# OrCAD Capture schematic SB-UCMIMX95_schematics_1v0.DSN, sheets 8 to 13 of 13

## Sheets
8 08. MIPI-CSI: size A3; title: MIPI-CSI
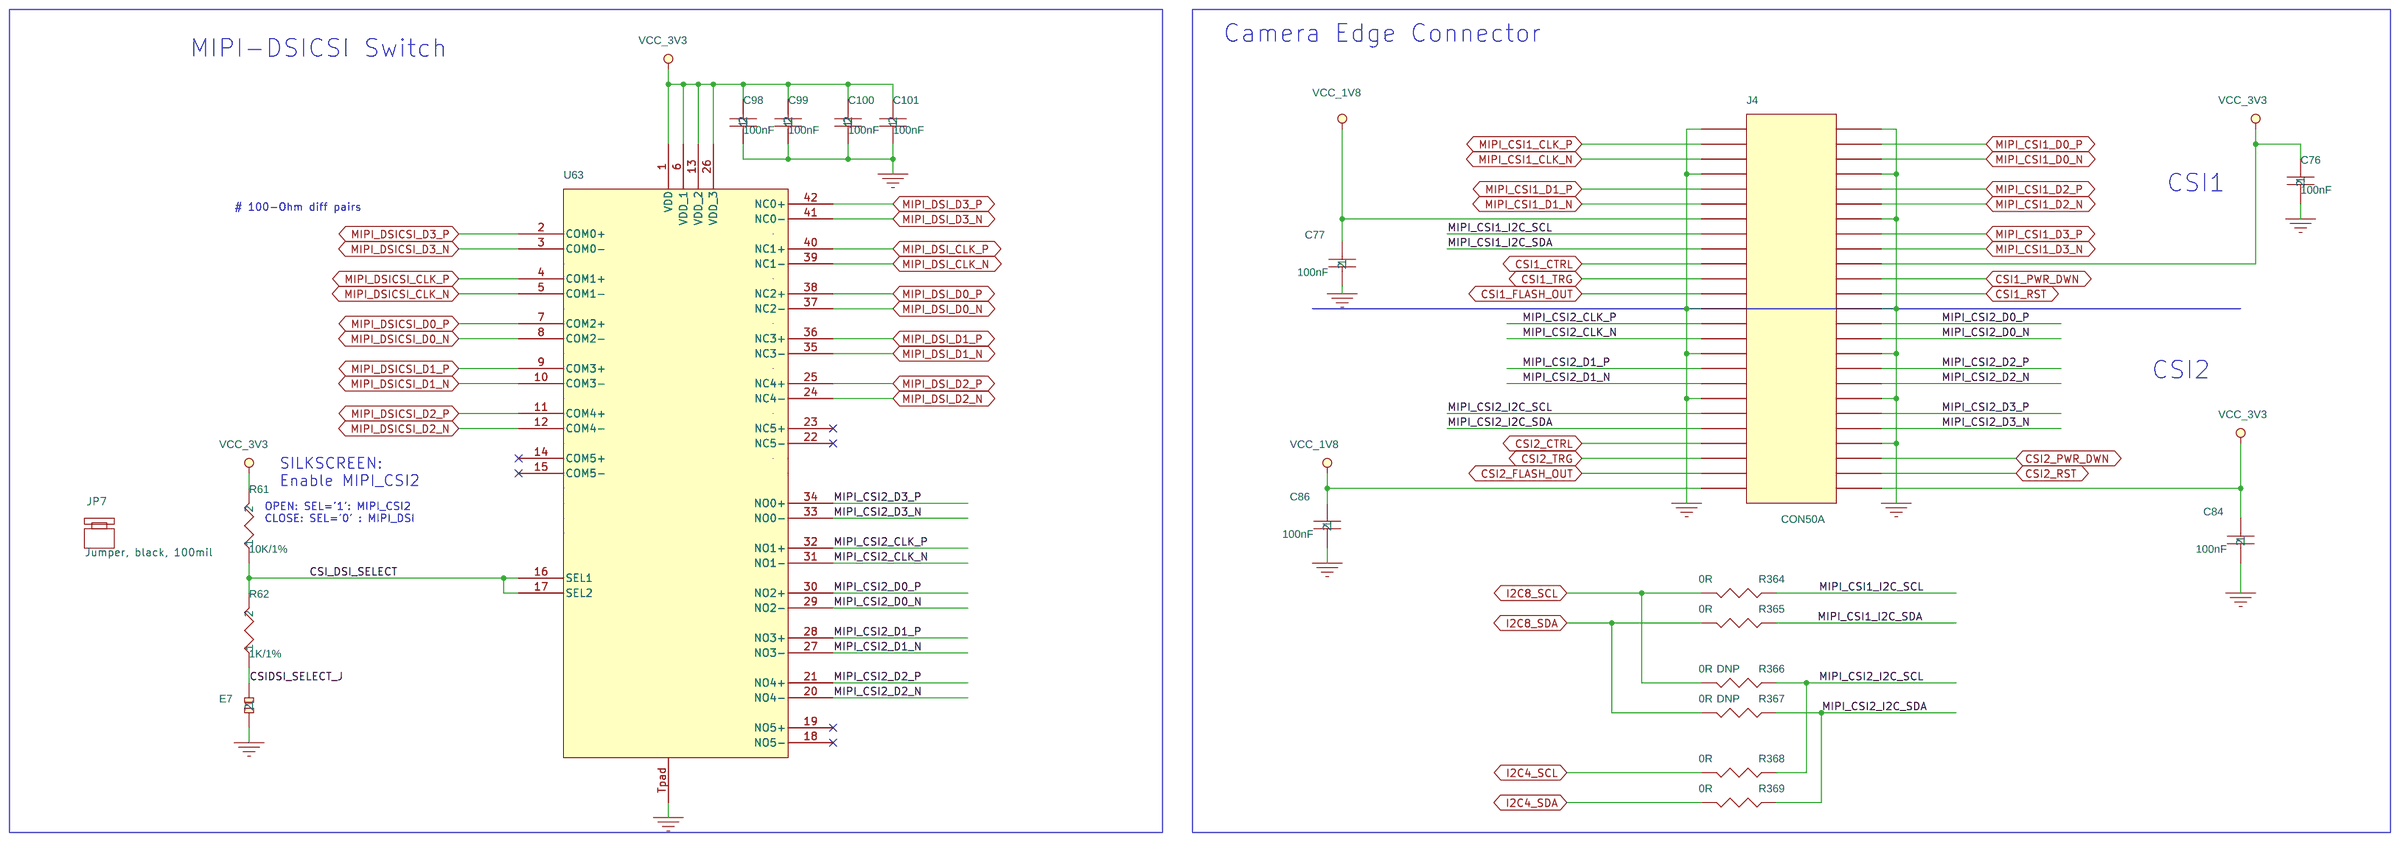
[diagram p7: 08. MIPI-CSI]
9 09. Audio Codec: size A3; title: Audio Codec
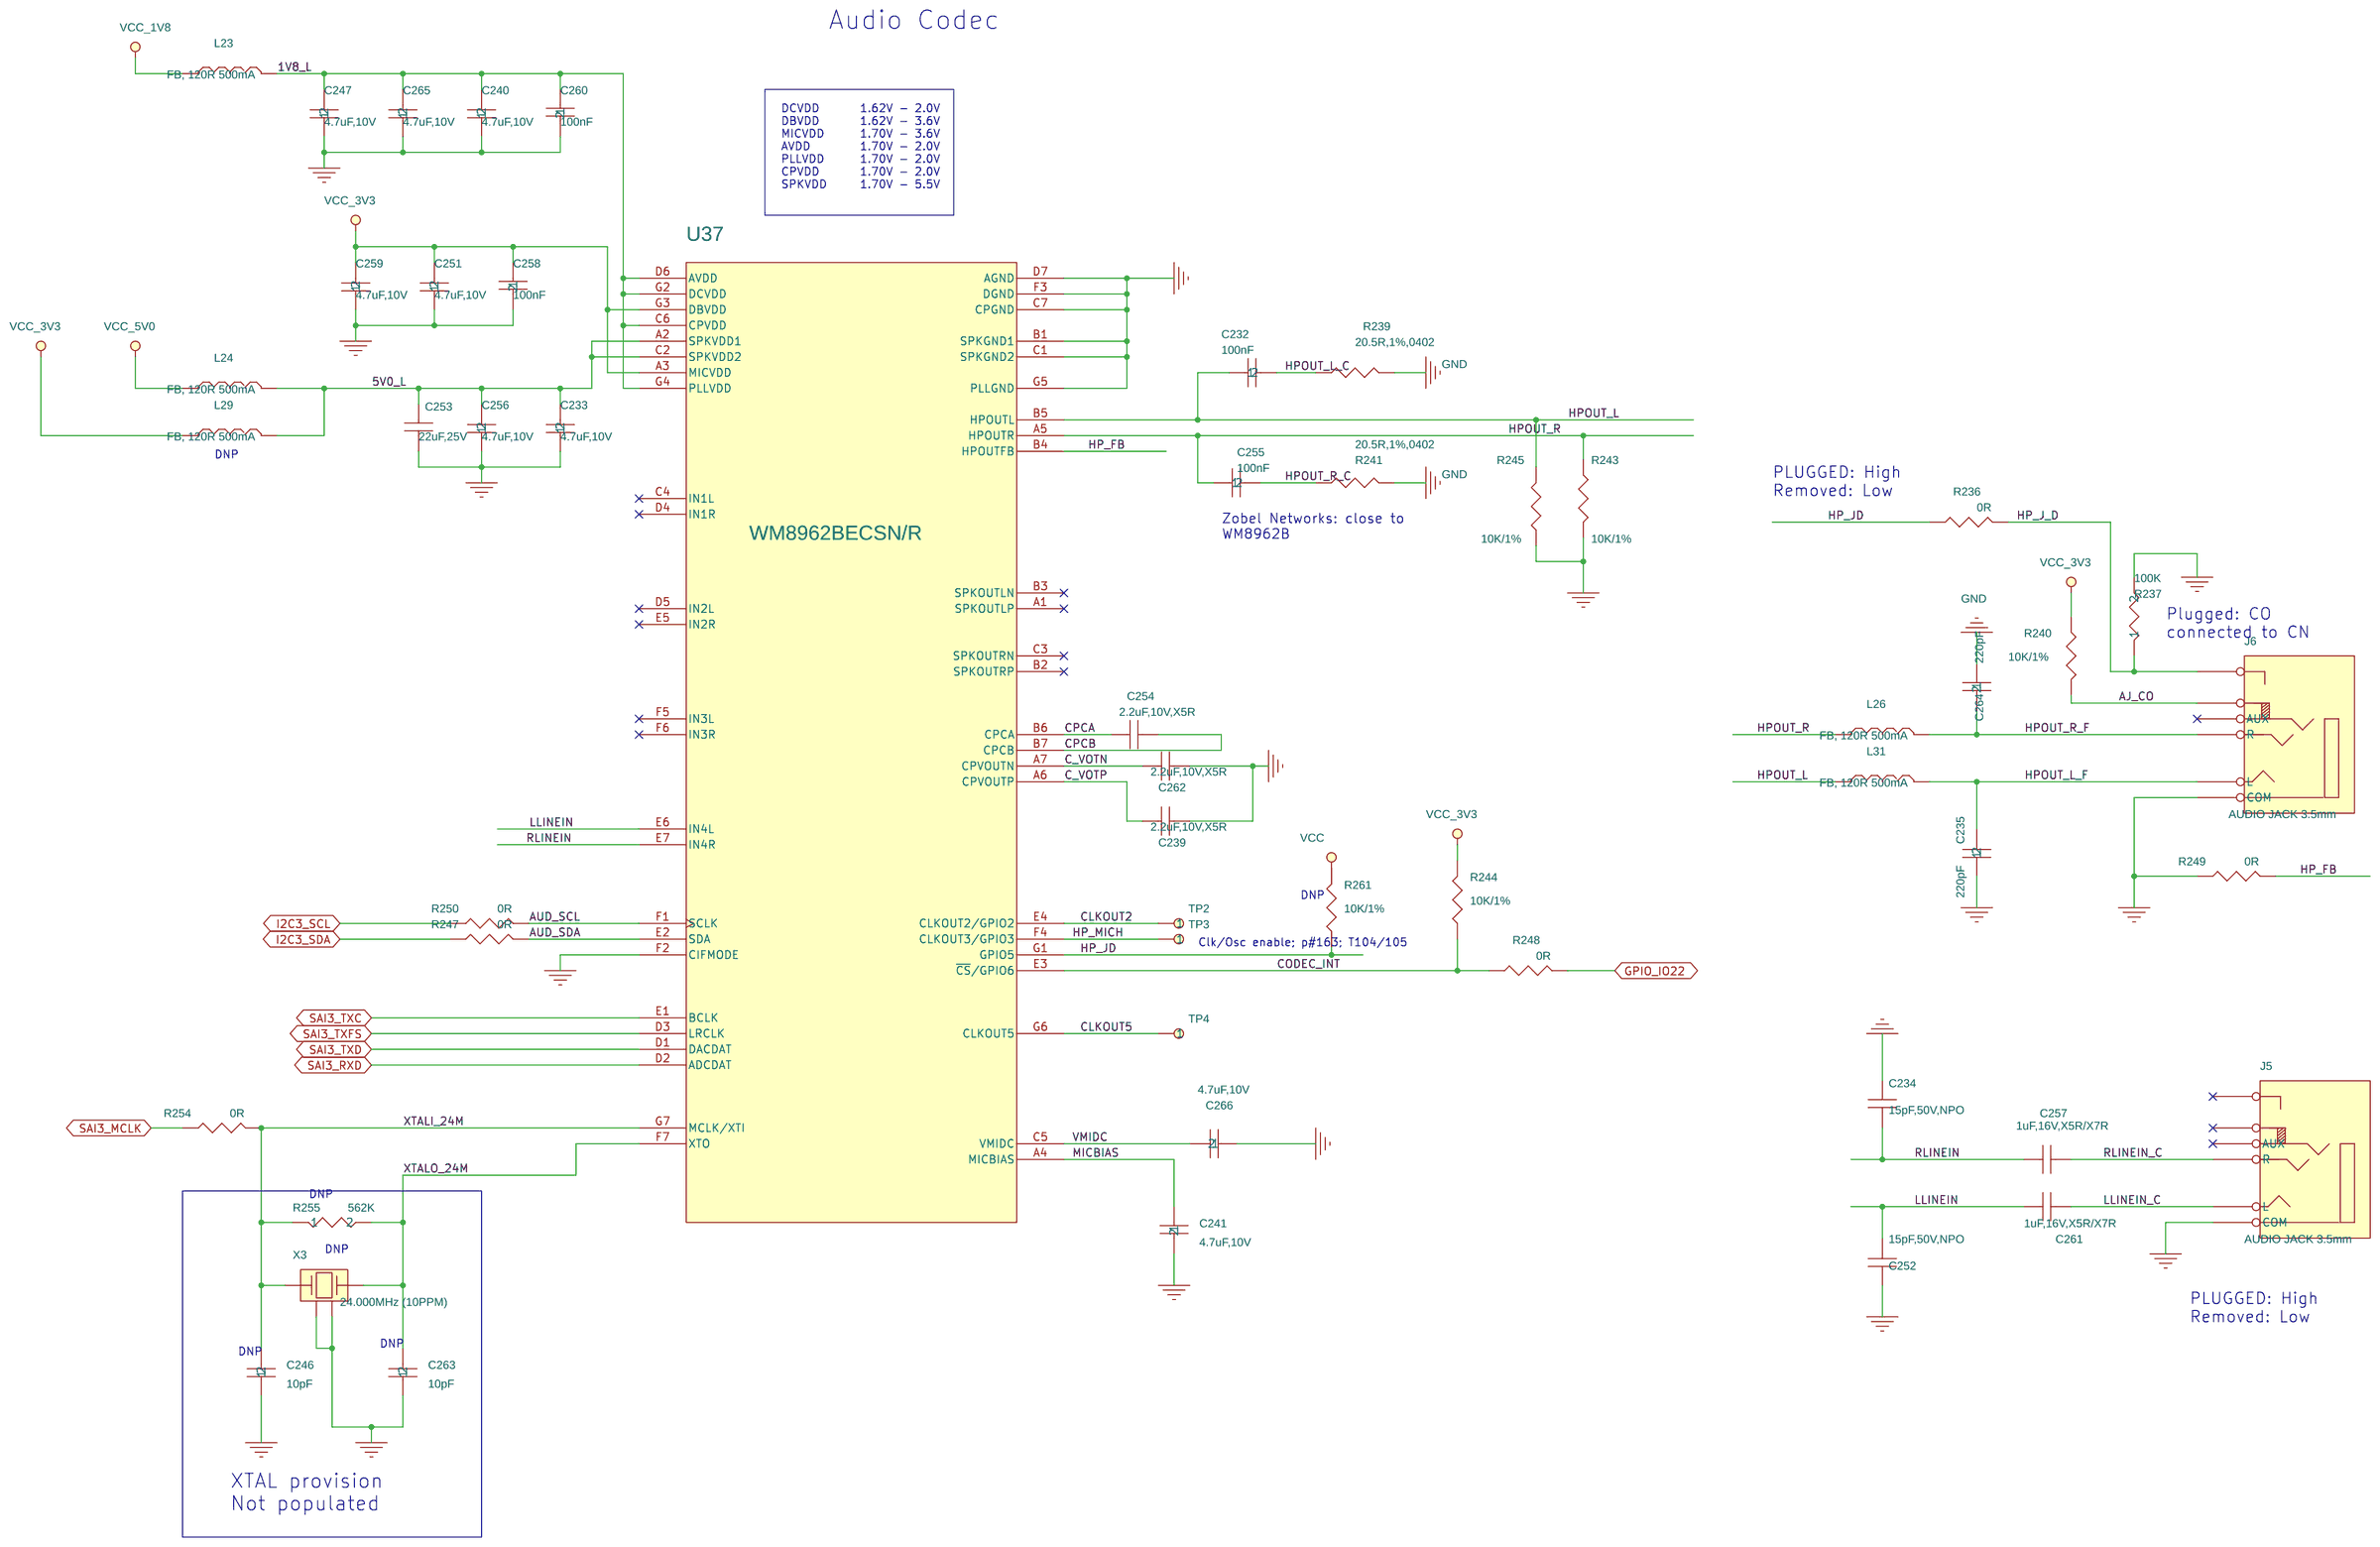
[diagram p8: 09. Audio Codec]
10 10. Octal SPI Flash, LEDs: size A3; title: Octal SPI Flash, LEDs
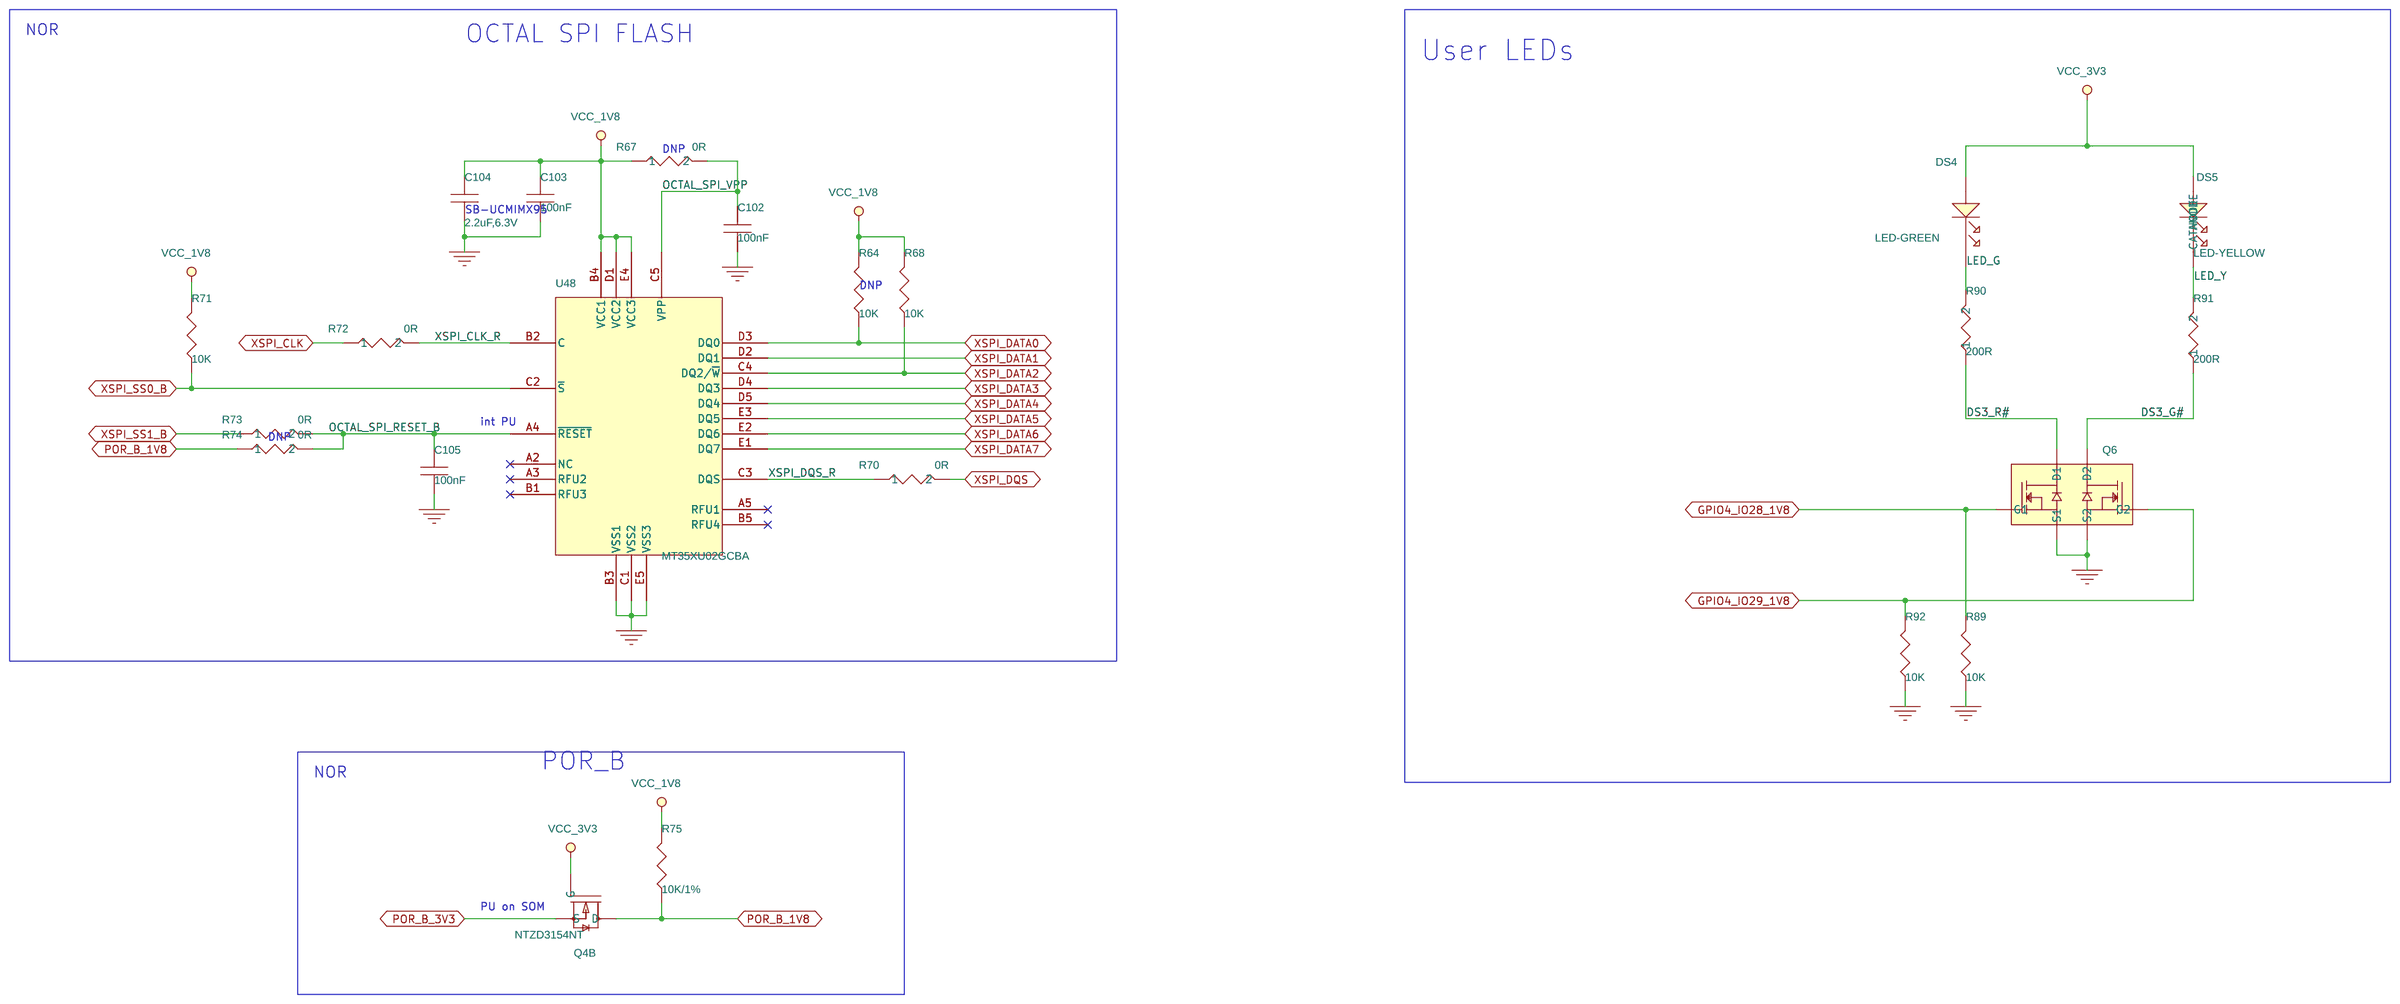
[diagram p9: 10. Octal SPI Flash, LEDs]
11 12. Power: size A3; title: Power
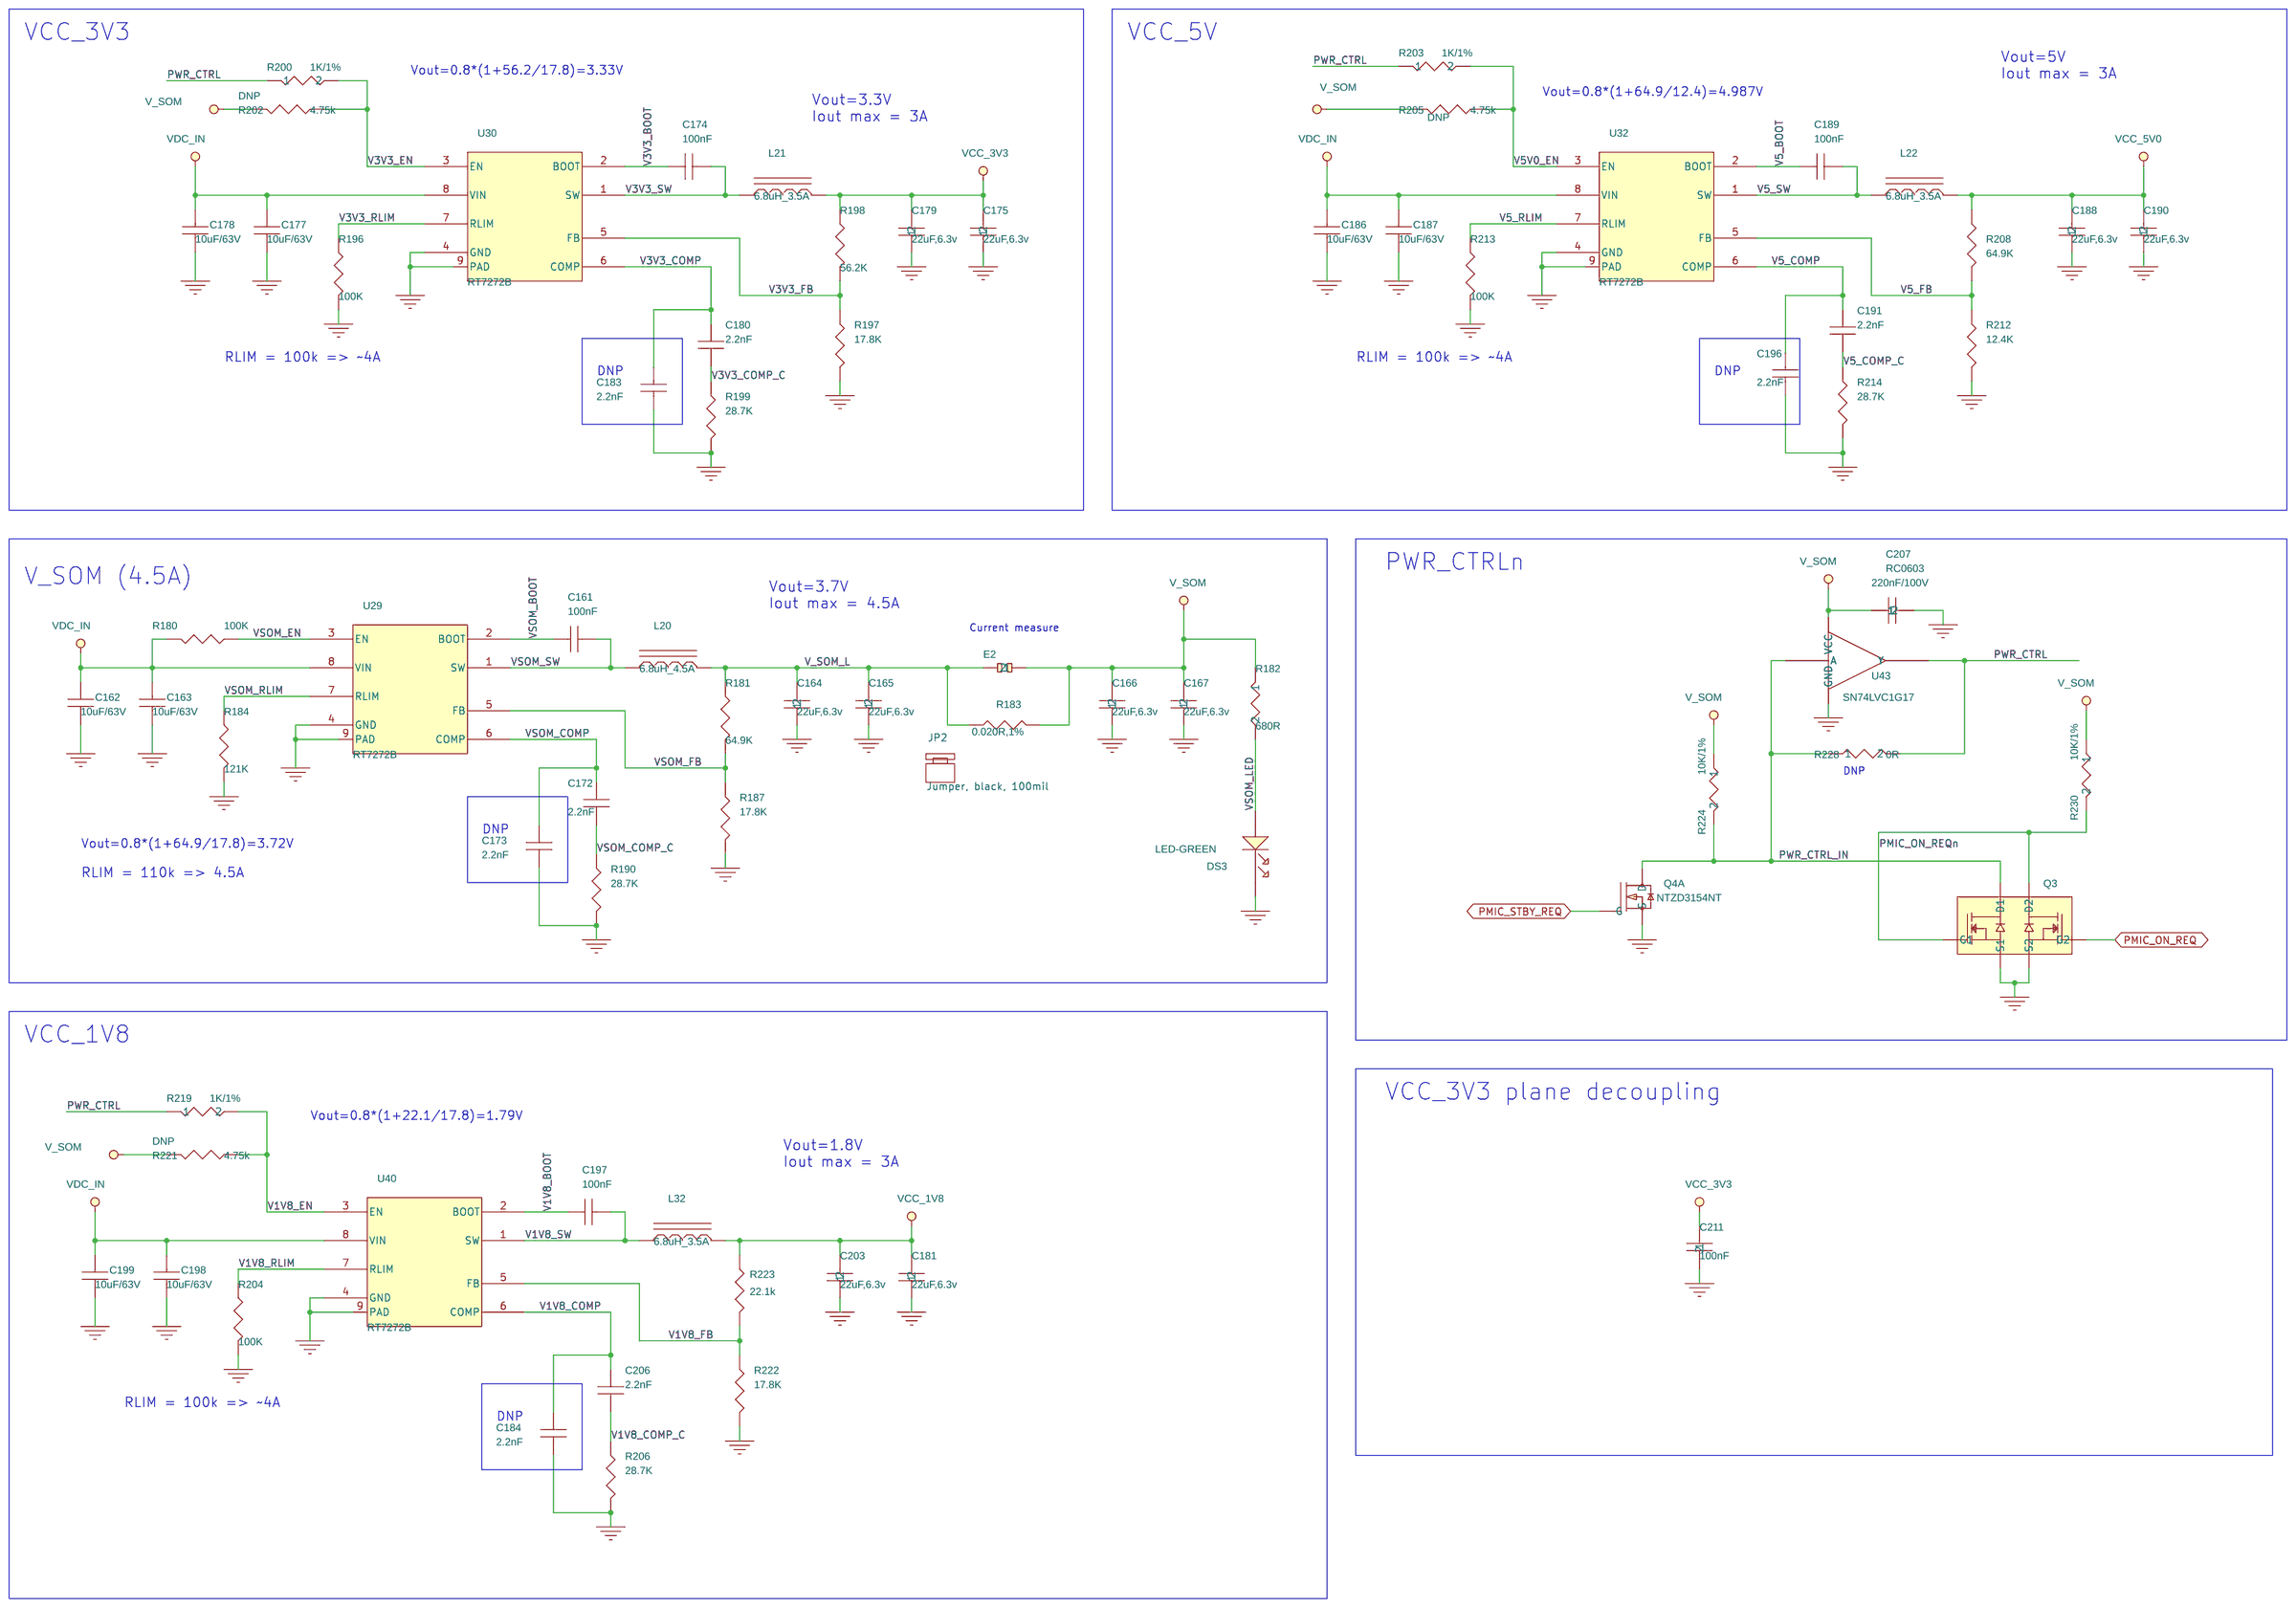
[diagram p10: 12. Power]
12 13. DC input and spacers: size A3; title: DC input and spacers
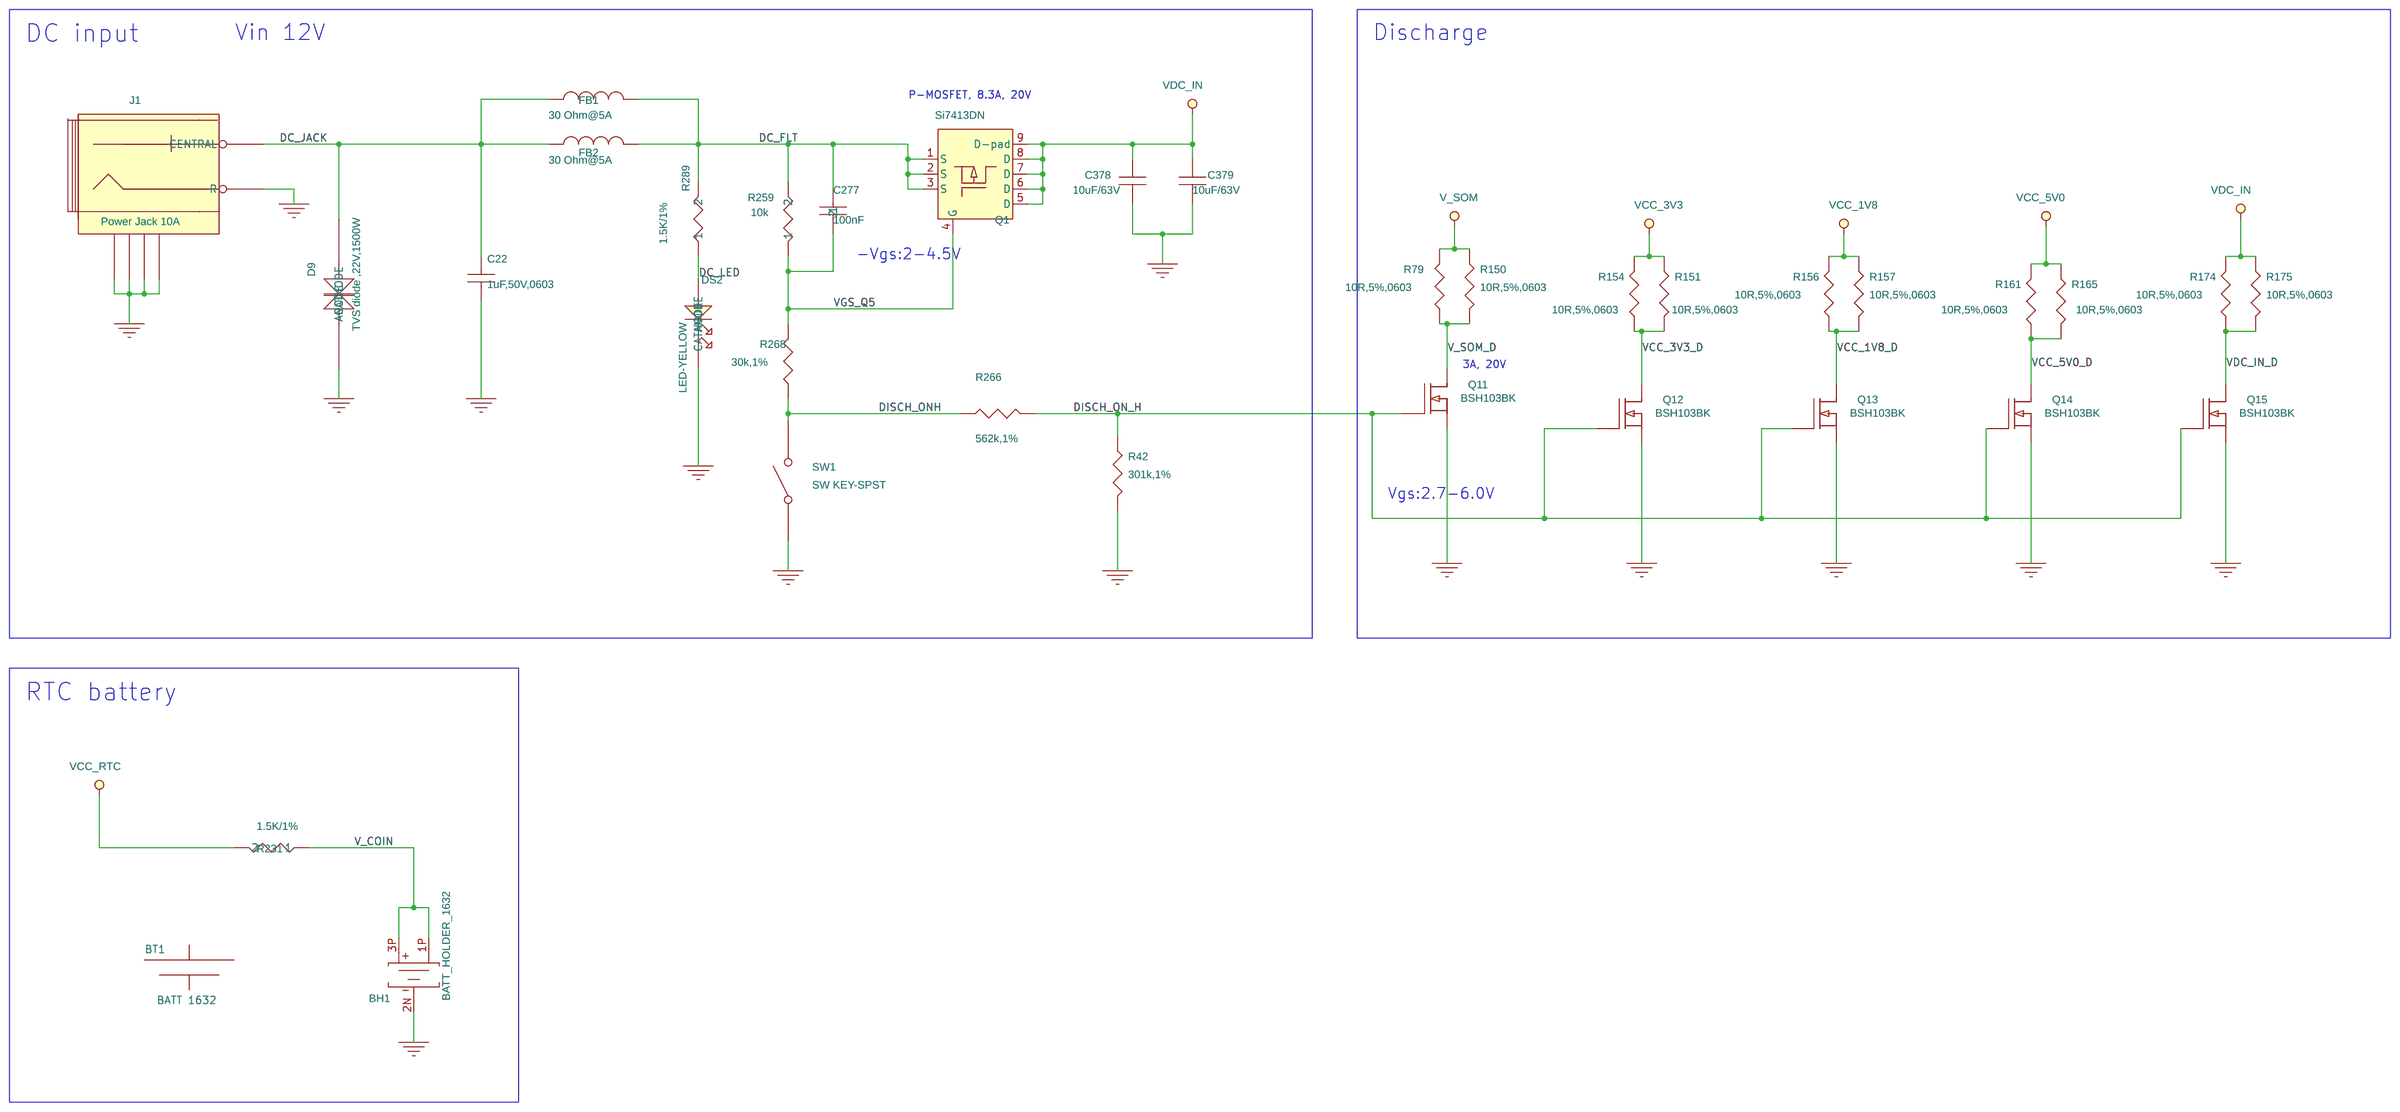
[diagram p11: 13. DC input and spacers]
13 11. I/O headers, JTAG, GPIO exp: size A3; title: I/O headers, JTAG, GPIO exp
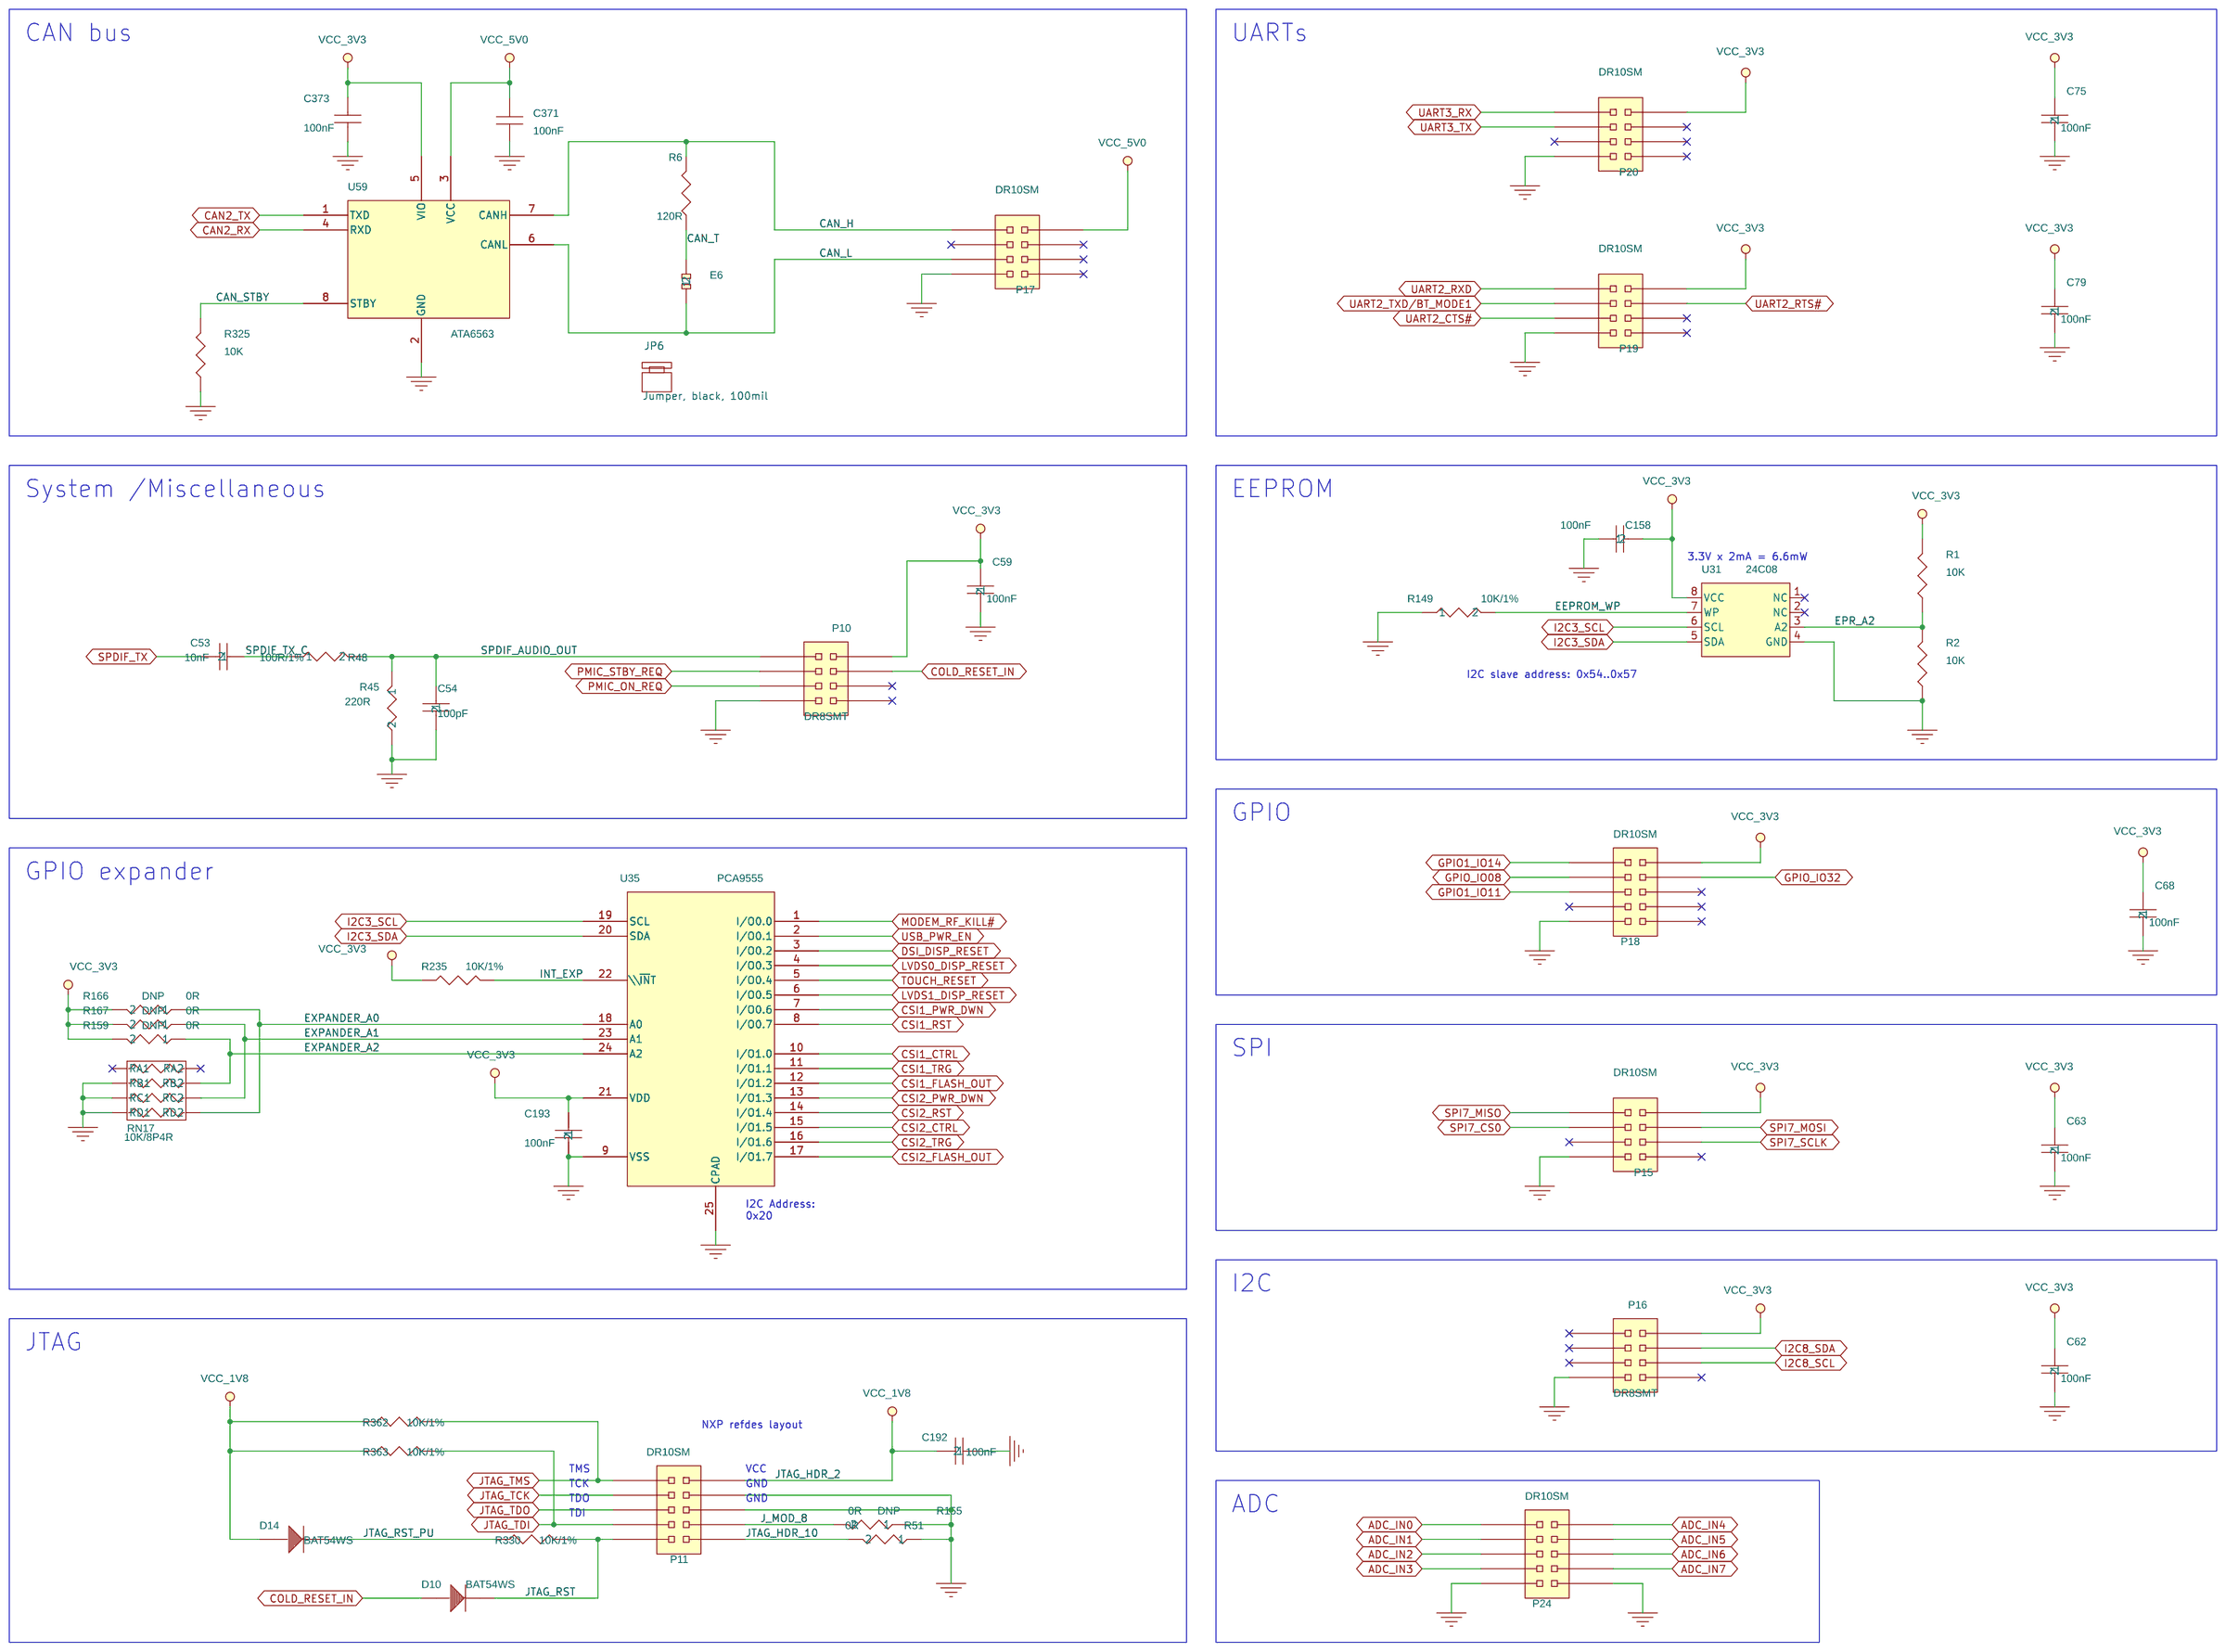
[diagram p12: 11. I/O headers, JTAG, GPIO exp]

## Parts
sheet 08. MIPI-CSI
C76  100nF  [RC0402]
C77  100nF  [RC0402]
C84  100nF  [RC0402]
C86  100nF  [RC0402]
C98  100nF  [RC0402]
C99  100nF  [RC0402]
C100  100nF  [RC0402]
C101  100nF  [RC0402]
E7  HDR1X2  [1X2THHDR]
J4  CON50A
JP7  Jumper, black, 100mil
R61  10K/1%  [RC0402]
R62  1K/1%  [RC0402]
R364  0R  [RC0402]
R365  0R  [RC0402]
R366  0R  [RC0402]
R367  0R  [RC0402]
R368  0R  [RC0402]
R369  0R  [RC0402]
U63  Value  [21-0181B_T423590M-1_MXM]
sheet 09. Audio Codec
C232  100nF  [RC0402]
C233  4.7uF,10V  [RC0402]
C234  15pF,50V,NPO  [RC0402]
C235  220pF  [RC0603]
C239  2.2uF,10V,X5R  [RC0402]
C240  4.7uF,10V  [RC0402]
C241  4.7uF,10V  [RC0402]
C246  10pF  [RC0402]
C247  4.7uF,10V  [RC0402]
C251  4.7uF,10V  [RC0402]
C252  15pF,50V,NPO  [RC0402]
C253  22uF,25V  [C0805]
C254  2.2uF,10V,X5R  [RC0402]
C255  100nF  [RC0402]
C256  4.7uF,10V  [RC0402]
C257  1uF,16V,X5R/X7R  [RC0402]
C258  100nF  [RC0402]
C259  4.7uF,10V  [RC0402]
C260  100nF  [RC0402]
C261  1uF,16V,X5R/X7R  [RC0402]
C262  2.2uF,10V,X5R  [RC0402]
C263  10pF  [RC0402]
C264  220pF  [RC0603]
C265  4.7uF,10V  [RC0402]
C266  4.7uF,10V  [RC0402]
J5  AUDIO JACK 3.5mm  [AJ35-4P-SW-SM]
J6  AUDIO JACK 3.5mm  [AJ35-4P-SW-SM]
L23  FB, 120R 500mA  [FB0402]
L24  FB, 120R 500mA  [FB0402]
L26  FB, 120R 500mA  [FB0402]
L29  FB, 120R 500mA  [FB0402]
L31  FB, 120R 500mA  [FB0402]
R236  0R  [RC0402]
R237  100K  [RC0402]
R239  20.5R,1%,0402  [RC0402]
R240  10K/1%  [RC0402]
R241  20.5R,1%,0402  [RC0402]
R243  10K/1%  [RC0402]
R244  10K/1%  [RC0402]
R245  10K/1%  [RC0402]
R247  0R  [RC0402]
R248  0R  [RC0402]
R249  0R  [RC0402]
R250  0R  [RC0402]
R254  0R  [RC0402]
R255  562K  [RC0402]
R261  10K/1%  [RC0402]
TP2  TESTPOINT SMT  [TESTPOINT]
TP3  TESTPOINT SMT  [TESTPOINT]
TP4  TESTPOINT SMT  [TESTPOINT]
U37  WM8962BECSN/R  [BGA49_0P5_3P62X4]
X3  24.000MHz (10PPM)  [OSC3225]
sheet 10. Octal SPI Flash, LEDs
C102  100nF  [RC0402]
C103  100nF  [RC0402]
C104  2.2uF,6.3V  [RC0402]
C105  100nF  [RC0402]
DS4  LED-GREEN  [LED-1206]
DS5  LED-YELLOW  [LED-1206]
Q6  0.5A,20V,Vgs max 6V  [SOT-563-6]
R64  10K  [RC0402]
R67  0R  [RC0402]
R68  10K  [RC0402]
R70  0R  [RC0402]
R71  10K  [RC0402]
R72  0R  [RC0402]
R73  0R  [RC0402]
R74  0R  [RC0402]
R75  10K/1%  [RC0402]
R89  10K  [RC0402]
R90  200R  [RC0402]
R91  200R  [RC0402]
R92  10K  [RC0402]
U48  MT35XU02GCBA  [PBGA24_1_6X8MM]
sheet 11. I/O headers, JTAG, GPIO exp
C53  10nF  [RC0402]
C54  100pF  [RC0402]
C59  100nF  [RC0402]
C62  100nF  [RC0402]
C63  100nF  [RC0402]
C68  100nF  [RC0402]
C75  100nF  [RC0402]
C79  100nF  [RC0402]
C158  100nF  [RC0402]
C192  100nF  [RC0402]
C193  100nF  [RC0402]
C371  100nF  [RC0402]
C373  100nF  [RC0402]
D10  BAT54WS  [SOD-323]
D14  BAT54WS  [SOD-323]
E6  HDR1X2  [1X2THHDR]
JP6  Jumper, black, 100mil
P10  DR8SMT  [2X4SMHDR]
P11  DR10SM  [2X5SMHDR]
P15  DR10SM  [2X4SMHDR]
P16  DR8SMT  [2X4SMHDR]
P17  DR10SM  [2X4SMHDR]
P18  DR10SM  [2X5SMHDR]
P19  DR10SM  [2X4SMHDR]
P20  DR10SM  [2X4SMHDR]
P24  DR10SM  [2X5SMHDR]
R1  10K  [RC0402]
R2  10K  [RC0402]
R6  120R  [RC0402]
R45  220R  [RC0402]
R48  100R/1%  [RC0402]
R51  0R  [RC0402]
R149  10K/1%  [RC0402]
R155  0R  [RC0402]
R159  0R  [RC0402]
R166  0R  [RC0402]
R167  0R  [RC0402]
R235  10K/1%  [RC0402]
R325  10K  [RC0402]
R330  10K/1%  [RC0402]
R362  10K/1%  [RC0402]
R363  10K/1%  [RC0402]
RN17  10K/8P4R  [RESNET8P0805]
U31  24C08  [MO-229VCED-2]
U35  PCA9555  [QFN4x4-24]
U59  ATA6563  [SOI8-150]
sheet 12. Power
C161  100nF  [RC0402]
C162  10uF/63V  [C1210H2_5]
C163  10uF/63V  [C1210H2_5]
C164  22uF,6.3v  [RC0603]
C165  22uF,6.3v  [RC0603]
C166  22uF,6.3v  [RC0603]
C167  22uF,6.3v  [RC0603]
C172  2.2nF  [RC0402]
C173  2.2nF  [RC0402]
C174  100nF  [RC0402]
C175  22uF,6.3v  [RC0603]
C177  10uF/63V  [C1210H2_5]
C178  10uF/63V  [C1210H2_5]
C179  22uF,6.3v  [RC0603]
C180  2.2nF  [RC0402]
C181  22uF,6.3v  [RC0603]
C183  2.2nF  [RC0402]
C184  2.2nF  [RC0402]
C186  10uF/63V  [C1210H2_5]
C187  10uF/63V  [C1210H2_5]
C188  22uF,6.3v  [RC0603]
C189  100nF  [RC0402]
C190  22uF,6.3v  [RC0603]
C191  2.2nF  [RC0402]
C196  2.2nF  [RC0402]
C197  100nF  [RC0402]
C198  10uF/63V  [C1210H2_5]
C199  10uF/63V  [C1210H2_5]
C203  22uF,6.3v  [RC0603]
C206  2.2nF  [RC0402]
C207  220nF/100V  [RC0603]
C211  100nF  [RC0402]
DS3  LED-GREEN  [LED-1206]
E2  HDR1X2  [1X2THHDR]
JP2  Jumper, black, 100mil
L20  6.8uH_4.5A  [IND6x5_5x3]
L21  6.8uH_3.5A  [IND6x5_5x3]
L22  6.8uH_3.5A  [IND6x5_5x3]
L32  6.8uH_3.5A  [IND6x5_5x3]
Q3  0.5A,20V,Vgs max 6V  [SOT-563-6]
Q4  NTZD3154NT  [SOT-563-6]  (sections A,B)
R180  100K  [RC0402]
R181  64.9K  [RC0402]
R182  680R  [RC0402]
R183  0.020R,1%  [R1206]
R184  121K  [RC0402]
R187  17.8K  [RC0402]
R190  28.7K  [RC0402]
R196  100K  [RC0402]
R197  17.8K  [RC0402]
R198  56.2K  [RC0402]
R199  28.7K  [RC0402]
R200  1K/1%  [RC0402]
R202  4.75k  [RC0402]
R203  1K/1%  [RC0402]
R204  100K  [RC0402]
R205  4.75k  [RC0402]
R206  28.7K  [RC0402]
R208  64.9K  [RC0402]
R212  12.4K  [RC0402]
R213  100K  [RC0402]
R214  28.7K  [RC0402]
R219  1K/1%  [RC0402]
R221  4.75k  [RC0402]
R222  17.8K  [RC0402]
R223  22.1k  [RC0402]
R224  10K/1%  [RC0402]
R228  0R  [RC0402]
R230  10K/1%  [RC0402]
U29  RT7272B  [PSOP-8-2X2]
U30  RT7272B  [PSOP-8-2X2]
U32  RT7272B  [PSOP-8-2X2]
U40  RT7272B  [PSOP-8-2X2]
U43  SN74LVC1G17
sheet 13. DC input and spacers
BH1  BATT_HOLDER_1632  [BattH16mm-SM]
BT1  BATT 1632
C22  1uF,50V,0603  [RC0603]
C277  100nF  [RC0402]
C378  10uF/63V  [C1210H2_5]
C379  10uF/63V  [C1210H2_5]
D9  TVS diode ,22V,1500W  [DO-214AB]
DS2  LED-YELLOW  [LED-1206]
FB1  30 Ohm@5A  [FB0603]
FB2  30 Ohm@5A  [FB0603]
J1  Power Jack 10A  [PJ-0810-TH]
Q1  Si7413DN  [Powerpak1212-8]
Q11  BSH103BK  [SOT23]
Q12  BSH103BK  [SOT23]
Q13  BSH103BK  [SOT23]
Q14  BSH103BK  [SOT23]
Q15  BSH103BK  [SOT23]
R42  301k,1%  [RC0402]
R79  10R,5%,0603  [RC0603]
R150  10R,5%,0603  [RC0603]
R151  10R,5%,0603  [RC0603]
R154  10R,5%,0603  [RC0603]
R156  10R,5%,0603  [RC0603]
R157  10R,5%,0603  [RC0603]
R161  10R,5%,0603  [RC0603]
R165  10R,5%,0603  [RC0603]
R174  10R,5%,0603  [RC0603]
R175  10R,5%,0603  [RC0603]
R231  1.5K/1%  [RC0402]
R259  10k  [RC0402]
R266  562k,1%  [RC0402]
R268  30k,1%  [RC0402]
R289  1.5K/1%  [RC0402]
SW1  SW KEY-SPST

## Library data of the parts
C63 C76 = 100nF,_10V,_X7R,_10%,_0402_4: CLABCONF0: SB-UCMIMX95
C68 C77 C260 = 100nF,_10V,_X7R,_10%,_0402_2: CLABCONF0: SB-UCMIMX95
C79 C84 = 100nF,_10V,_X7R,_10%,_0402_5: CLABCONF0: SB-UCMIMX95
C75 C86 C255 = 100nF,_10V,_X7R,_10%,_0402_3: CLABCONF0: SB-UCMIMX95
C98 C158 C258 = 100nF,_10V,_X7R,_10%,_0402_1: CLABCONF0: SB-UCMIMX95
C59 C99 = 100nF,_10V,_X7R,_10%,_0402_7: CLABCONF0: SB-UCMIMX95
C62 C100 C232 C277 = 100nF,_10V,_X7R,_10%,_0402: CLABCONF0: SB-UCMIMX95
C101 C192 = 100nF,_10V,_X7R,_10%,_0402_6: CLABCONF0: SB-UCMIMX95
E2 E6 E7 = HDR_1x2_100MIL_TH_JUMPER: CLABCONF0: SB-UCMIMX95
J4 = CON50A: CLABCONF0: SB-UCMIMX95; P/N: 182K05001S
JP2 JP6 JP7 = Jumper,_black,_100mil: CLABCONF0: SB-UCMIMX95
R61 R230 = 10K,1%,0402,1_16W_1: CLABCONF0: SB-UCMIMX95
R62 = 10K,1%,0402,1_16W: CLABCONF0: SB-UCMIMX95; P/N: 161C10011S
R364 = 0R,_0402_0_2: CLABCONF0: SB-UCMIMX95; P/N: 161C00005S
R365 = 0R,_0402_0_5: CLABCONF0: SB-UCMIMX95; P/N: 161C00005S
R366 = 0R,_0402_0: CLABCONF0: DNP; P/N: 161C00005S
R367 = 0R,_0402_0_3: CLABCONF0: DNP; P/N: 161C00005S
R368 = 0R,_0402_0_1: CLABCONF0: SB-UCMIMX95; P/N: 161C00005S
R369 = 0R,_0402_0_4: CLABCONF0: SB-UCMIMX95; P/N: 161C00005S
U63 = MAX14998ETOT: CLABCONF0: SB-UCMIMX95
C233 = 15pF,_50V,_NPO,_5%,_0402_2: CLABCONF0: SB-UCMIMX95; P/N: 151B47500S
C234 C252 = CAP_NP: CLABCONF0: SB-UCMIMX95; P/N: 151D15000S
C235 = 220pF,50V,NPO,0603: CLABCONF0: SB-UCMIMX95
C239 C254 C262 = CAP_NP: CLABCONF0: SB-UCMIMX95; P/N: 151B22500S
C240 = 15pF,_50V,_NPO,_5%,_0402_6: CLABCONF0: SB-UCMIMX95; P/N: 151B47500S
C241 = 15pF,_50V,_NPO,_5%,_0402_1: CLABCONF0: SB-UCMIMX95; P/N: 151B47500S
C246 = 10pF,50V,NPO,_5%,_0402_1: CLABCONF0: DNP
C247 = 15pF,_50V,_NPO,_5%,_0402: CLABCONF0: SB-UCMIMX95; P/N: 151B47500S
C251 = 15pF,_50V,_NPO,_5%,_0402_5: CLABCONF0: SB-UCMIMX95; P/N: 151B47500S
C253 = CAP_NP: CLABCONF0: SB-UCMIMX95; P/N: 151C22620S
C256 = 15pF,_50V,_NPO,_5%,_0402_8: CLABCONF0: SB-UCMIMX95; P/N: 151B47500S
C257 C261 = CAP_NP: CLABCONF0: SB-UCMIMX95; P/N: 151C10500S
C259 = 15pF,_50V,_NPO,_5%,_0402_3: CLABCONF0: SB-UCMIMX95; P/N: 151B47500S
C263 = 10pF,50V,NPO,_5%,_0402: CLABCONF0: DNP
C264 = 220pF,50V,NPO,0603_1: CLABCONF0: SB-UCMIMX95
C265 = 15pF,_50V,_NPO,_5%,_0402_4: CLABCONF0: SB-UCMIMX95; P/N: 151B47500S
C266 = 15pF,_50V,_NPO,_5%,_0402_7: CLABCONF0: SB-UCMIMX95; P/N: 151B47500S
J5 J6 = Audio_JACK,_STEREO+AUX+SW_3.5mm: CLABCONF0: SB-UCMIMX95
L23 L24 L26 L31 = Ferrit_330R-100Mhz,1.2A: CLABCONF0: SB-UCMIMX95; P/N: 147D12102S
L29 = Ferrit_330R-100Mhz,1.2A: CLABCONF0: DNP; P/N: 147D12102S
R236 = 0R,_0402_0_4: CLABCONF0: SB-UCMIMX95
R237 = 100K,_0402: CLABCONF0: SB-UCMIMX95; P/N: 161C10031S
R239 R241 = RESISTOR: CLABCONF0: SB-UCMIMX95; P/N: 161C20R51S
R92 R240 = 10K,1%,0402,1_16W_0_3: CLABCONF0: SB-UCMIMX95
R243 = 10K,1%,0402,1_16W_0_1: CLABCONF0: SB-UCMIMX95
R244 = 10K,1%,0402,1_16W_0_4: CLABCONF0: SB-UCMIMX95
R1 R89 R245 = 10K,1%,0402,1_16W_0: CLABCONF0: SB-UCMIMX95
R247 = 0R,_0402_0: CLABCONF0: SB-UCMIMX95
R248 = 0R,_0402_0_2: CLABCONF0: SB-UCMIMX95
R249 = 0R,_0402_0_5: CLABCONF0: SB-UCMIMX95
R250 = 0R,_0402_0_1: CLABCONF0: SB-UCMIMX95
R254 = 0R,_0402_0_3: CLABCONF0: SB-UCMIMX95
R255 = 10M,5%,0402,1_16W: CLABCONF0: DNP; P/N: 161C56231S
R261 = 10K,1%,0402,1_16W_0_2: CLABCONF0: DNP
TP2-TP4 = TESTPOINT: CLABCONF0: DNP; P/N: 188Z01370S
U37 = WM8962_BGA_49P_A: IC AUDIO CODEC 24BIT DAC 2 CH ADC 1.8V BGA49; 3D_Mechanical_Footprint_File: ftp://fcl.am.freescale.net/ALLEGRO/step/BGA49_0P5_3P62X4.STEP; AGILE_PN: 315-80353; CLABCONF0: SB-UCMIMX95; HEIGHT: 0.75MM; MFG_NAME01: WOLFSON MICROELECTRONICS; P/N: 117A10070S; ROHS: Yes; VOLTAGE: 1.8V
X3 = XTAL,24.000Mhz,100ppm,Ind,3x5mm: CLABCONF0: DNP; P/N: 141B24605I
C102 C103 C105 = 1uF,X5R,6.3V,0402: CLABCONF0: NOR; P/N: 151B10400S
C104 = Cap_1uF,X5R,6.3V,0402: CLABCONF0: SB-UCMiMX95; P/N: 151A22500S
DS3 DS4 = LED-GREEN_1206_2: CLABCONF0: SB-UCMIMX95
DS2 DS5 = LED-RED_1206: CLABCONF0: SB-UCMIMX95; P/N: 139A10110S
Q6 = DUAL_N-MOSFET,_0.5A_20V: CLABCONF0: SB-UCMIMX95
R64 = 10K,1%,0402,1_16W_0_5: CLABCONF0: DNP; Group: Always
R67 = 0R,_0402_4: CLABCONF0: DNP
R68 = 10K,1%,0402,1_16W_0_4: CLABCONF0: NOR; Group: Always
R70 = 0R,_0402_3: CLABCONF0: NOR
R71 = 10K,1%,0402,1_16W_0_2: CLABCONF0: NOR; Group: Always
R72 = 0R,_0402_2: CLABCONF0: NOR
R73 = 0R,_0402_1: CLABCONF0: NOR
R74 = 0R,_0402: CLABCONF0: DNP
R75 = 10K,1%,0402,1_16W_0_1: CLABCONF0: NOR; P/N: 161C10021S
R90 = 348R,1%,0402,1_16W: CLABCONF0: SB-UCMIMX95; P/N: 161C20001S
R91 = 348R,1%,0402,1_16W_1: CLABCONF0: SB-UCMIMX95; P/N: 161C20001S
U48 = MT35XU512ABA1G12_0: IC MEM FLASH SERIAL NOR 512MB 1.7-2.0V AUTO T-PBGA24; CLABCONF0: NOR; EN: 301-2-00388; HEIGHT: 1.2MM; MFG_NAME01: MICRON; MFG_PN01: MT35XU512ABA1G12-0AATES; P/N: 111S32800S; ROHS: Yes
C53 = 10nF,_25V,_X7R,_10%,_0402: CLABCONF0: SB-UCMIMX95
C54 = 100pF,_50V,_NPO,_5%,_0402: CLABCONF0: SB-UCMIMX95
C193 = 100nF,_10V,_X7R,_10%,_0402_8: CLABCONF0: SB-UCMIMX95
C371 C373 = 100nF,_10V,_X7R,_10%,_0402_0: CLABCONF0: SB-UCMIMX95
D10 D14 = BAT54WS_0: CLABCONF0: SB-UCMIMX95
P10 P16 = HDR_2x7_100MIL_RA_TH_SHRD_0: CLABCONF0: SB-UCMIMX95; P/N: 190C00801S
P11 P18 P24 = HDR_2x5_100MIL_SMT: CLABCONF0: SB-UCMIMX95
P15 P17 P19 P20 = HDR_2x5_100MIL_SMT_2: CLABCONF0: SB-UCMIMX95; P/N: 190C00801S
R2 = 10K,1%,0402,1_16W_0_2: CLABCONF0: SB-UCMIMX95
R6 = 0R,_0402_0: CLABCONF0: SB-UCMIMX95; Group: Always; P/N: 161C12001S
R45 = 220R,5%,0402,1_16W: CLABCONF0: SB-UCMIMX95
R48 = 100R,1%,0402,1_16W: CLABCONF0: SB-UCMIMX95
R51 = 0R,_0402_1: CLABCONF0: SB-UCMIMX95
R149 R224 = 10K,1%,0402,1_16W: CLABCONF0: SB-UCMIMX95
R155 = 0R,_0402_1_4: CLABCONF0: DNP
R159 = 0R,_0402_1_1: CLABCONF0: DNP
R166 = 0R,_0402_1_3: CLABCONF0: DNP
R167 = 0R,_0402_1_2: CLABCONF0: DNP
R235 = 10K,1%,0402,1_16W_0_5: CLABCONF0: SB-UCMIMX95
R325 = 10K,1%,0402,1_16W_0_6: CLABCONF0: SB-UCMIMX95
R330 = 10K,1%,0402,1_16W_0_4: CLABCONF0: DNP
R362 = 10K,1%,0402,1_16W_0_3: CLABCONF0: DNP
R363 = 10K,1%,0402,1_16W_0_1: CLABCONF0: DNP
RN17 = RN,10K,8P4R@0805: CLABCONF0: SB-UCMIMX95
U31 = 24C02,_serial_EE,_2KB,_I2C_0: CLABCONF0: SB-UCMIMX95; P/N: 111S31000S
U35 = PCA9555_1: CLABCONF0: SB-UCMIMX95
U59 = ATA6563: CLABCONF0: SB-UCMIMX95; P/N: 116A00380S
C161 C174 C189 C197 = 100nF,_10V,_X7R,_10%,_0402_0: CLABCONF0: SB-UCMIMX95; Group: LAN2
C162 C163 = 22uF_25V: CLABCONF0: SB-UCMIMX95; P/N: 151D10630S
C164 = 100nF,_10V,_X7R,_10%,_0402_6: CLABCONF0: SB-UCMIMX95; P/N: 151B22610S
C165 = 100nF,_10V,_X7R,_10%,_0402_9: CLABCONF0: SB-UCMIMX95; P/N: 151B22610S
C166 = 100nF,_10V,_X7R,_10%,_0402_10: CLABCONF0: SB-UCMIMX95; P/N: 151B22610S
C167 = 100nF,_10V,_X7R,_10%,_0402_3: CLABCONF0: SB-UCMIMX95; P/N: 151B22610S
C172 = 2.2nF,_50V,_X7R,_10%,_0402: CLABCONF0: SB-UCMIMX95
C173 = 2.2nF,_50V,_X7R,_10%,_0402_6: CLABCONF0: DNP
C175 = 100nF,_10V,_X7R,_10%,_0402_2: CLABCONF0: SB-UCMIMX95; P/N: 151B22610S
C177 C178 C186 C187 C198 C199 C378 C379 = 22uF_25V: CLABCONF0: SB-UCMIMX95; P/N: 151E10680S
C179 = 100nF,_10V,_X7R,_10%,_0402_8: CLABCONF0: SB-UCMIMX95; P/N: 151B22610S
C180 = 2.2nF,_50V,_X7R,_10%,_0402_1: CLABCONF0: SB-UCMIMX95
C181 = 100nF,_10V,_X7R,_10%,_0402_4: CLABCONF0: SB-UCMIMX95; P/N: 151B22610S
C183 = 2.2nF,_50V,_X7R,_10%,_0402_3: CLABCONF0: DNP
C184 = 2.2nF,_50V,_X7R,_10%,_0402_4: CLABCONF0: DNP
C188 = 100nF,_10V,_X7R,_10%,_0402: CLABCONF0: SB-UCMIMX95; P/N: 151B22610S
C190 = 100nF,_10V,_X7R,_10%,_0402_7: CLABCONF0: SB-UCMIMX95; P/N: 151B22610S
C191 = 2.2nF,_50V,_X7R,_10%,_0402_7: CLABCONF0: SB-UCMIMX95
C196 = 2.2nF,_50V,_X7R,_10%,_0402_2: CLABCONF0: DNP
C203 = 100nF,_10V,_X7R,_10%,_0402_5: CLABCONF0: SB-UCMIMX95; P/N: 151B22610S
C206 = 2.2nF,_50V,_X7R,_10%,_0402_5: CLABCONF0: SB-UCMIMX95
C207 = 100nF,_10V,_X7R,_10%,_0402_11: CLABCONF0: SB-UCMIMX95; P/N: 151E22410S
C211 = 100nF,_10V,_X7R,_10%,_0402_1: CLABCONF0: SB-UCMIMX95; P/N: 151B10400S
L20 = IND_6.8uH_3.5A: CLABCONF0: SB-UCMIMX95; P/N: 147A6R803S
L21 L22 L32 = IND_6.8uH_3.5A: CLABCONF0: SB-UCMIMX95; P/N: 147A6R802S
Q3 = DUAL_N-MOSFET,_0.5A_20V: CLABCONF0: DNP
Q4 = N-MOSFET_Dual: CLABCONF0: SB-UCMIMX95; P/N: 131D31540S
R180 R196 R204 R213 = 100K,_0402_0: CLABCONF0: SB-UCMIMX95; P/N: 161C10031S
R181 R208 = 10.5K_1%,0402: CLABCONF0: SB-UCMIMX95; P/N: 161C64921S
R182 = 47K,_0402: CLABCONF0: SB-UCMIMX95; P/N: 161C68001S
R183 = RESISTOR: CLABCONF0: SB-UCMIMX95; P/N: 161G02011S; Part Name: Res., 0.020R, 1%, 1206, 1/2W (Current sense)
R184 = 100K,_0402_0: CLABCONF0: SB-UCMIMX95; P/N: 161C12131S
R187 R197 R222 = 2.37K_1%,_0402: CLABCONF0: SB-UCMIMX95; P/N: 161C17821S
R190 R199 R206 R214 = 40.2k_1%: CLABCONF0: SB-UCMIMX95; P/N: 161C28721S
R198 = 10.5K_1%,0402: CLABCONF0: SB-UCMIMX95; P/N: 161C56221S
R200 = 1K,1%,0402,1_16W_2: CLABCONF0: SB-UCMIMX95; Group: CAN
R202 R205 R221 = 100K,_0402_0: CLABCONF0: DNP; P/N: 161C47511S
R203 = 1K,1%,0402,1_16W_1: CLABCONF0: SB-UCMIMX95; Group: CAN
R212 = 2.37K_1%,_0402: CLABCONF0: SB-UCMIMX95; P/N: 161C12421S
R219 = 1K,1%,0402,1_16W: CLABCONF0: SB-UCMIMX95; Group: CAN
R223 = RESISTOR: CLABCONF0: SB-UCMIMX95; P/N: 161C22121S
R228 = 0R,_0402: CLABCONF0: SB-UCMIMX95
U29 U30 U32 U40 = RT7272B,Converter,3A,36V: CLABCONF0: SB-UCMIMX95; P/N: 123V30000S
U43 = SN74LVC1G17: CLABCONF0: SB-UCMIMX95; P/N: 106D90000S
BH1 = BATT_HOLDER_1: CLABCONF0: SB-UCMIMX95; P/N: 190Z00300S
BT1 = BATT_2032: CLABCONF0: SB-UCMIMX95; P/N: 210C30006
C22 = CAP_NP: CLABCONF0: SB-UCMIMX95; P/N: 151D10510S; Part Name: Cap., 1uF, 50V, X5R/X7R, 10%, 0603
D9 = Diode_,TVS_,15V,1500W_0: CLABCONF0: SB-UCMIMX95; P/N: 132D10030S
FB1 = Ferrite_bead_,_30_Ohm@5A_1: CLABCONF0: SB-UCMIMX95
FB2 = Ferrite_bead_,_30_Ohm@5A: CLABCONF0: SB-UCMIMX95
J1 = DC_Jack_,5.5_2.5,10A,20V: CLABCONF0: SB-UCMIMX95
Q1 = Si7413DN: CLABCONF0: SB-UCMIMX95
Q11-Q15 = MOSFET_N_SOT23: CLABCONF0: SB-UCMIMX95; P/N: 131D10160S
R42 = RESISTOR: CLABCONF0: SB-UCMIMX95; P/N: 161C30131S; Part Name: Res., 301K, 1%, 0402, 1/16W
R79 R150 R151 R154 R156 R157 R161 R165 R174 R175 = RESISTOR: CLABCONF0: SB-UCMIMX95; P/N: 161D10R05S; Part Name: Res., 10R, 5%, 0603
R231 = 1.5K_1%,_0402: CLABCONF0: SB-UCMIMX95
R259 = 1M_,5%,_0402: CLABCONF0: SB-UCMIMX95; P/N: 161C10021S
R266 = RESISTOR: CLABCONF0: SB-UCMIMX95; P/N: 161C56231S; Part Name: Res., 562K, 1%, 0402, 1/16W
R268 = RESISTOR: CLABCONF0: SB-UCMIMX95; P/N: 161C30021S; Part Name: Res., 30K, 1%, 0402, 1/16W
R289 = 1.5K_1%,_0402_1: CLABCONF0: SB-UCMIMX95
SW1 = SW_KEY-SPST: CLABCONF0: SB-UCMIMX95; P/N: 170F10010

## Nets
1V8_L: C240.2 C247.2 C260.1 C265.2 L23.1 U37.C6(CPVDD) U37.D6(AVDD) U37.G2(DCVDD) U37.G4(PLLVDD)
5V0_L: C233.2 C253.1 C256.2 L24.1 L29.1 U37.A2(SPKVDD1) U37.C2(SPKVDD2)
GND: BH1.2N(-) C22.2 C54.2 C59.2 C62.2 C63.2 C68.2 C75.2 C76.2 C77.2 C79.2 C84.2 C86.2 C98.1 C99.1 C100.1 C101.1 C102.2 C103.2 C104.2 C105.2 C158.1 C162.2 C163.2 C164.1 C165.1 C166.1 C167.1 C173.2 C175.1 C177.2 C178.2 C179.1 C181.1 C183.2 C184.2 C186.2 C187.2 C188.1 C190.1 C192.1 C193.2 C196.2 C198.2 C199.2 C203.1 C207.2 C211.2 C233.1 C234.1 C235.1 C239.2 C240.1 C241.2 C246.1 C247.1 C251.1 C252.1 C253.2 C256.1 C258.2 C259.1 C260.2 C262.2 C263.1 C264.1 C265.1 C266.1 C371.1 C373.2 C378.2 C379.2 D9.ANODE DS2.CATHODE DS3.CATHODE E7.2 J1.2(R) J1.SH1 J1.SH2 J1.SH3 J1.SH4 J4.1 J4.2 J4.7 J4.8 J4.13 J4.25 J4.26 J4.31 J4.32 J4.37 J4.38 J4.43 J5.1(COM) J6.1(COM) P10.8 P11.4 P11.6 P15.8 P16.8 P17.8 P18.10 P19.8 P20.8 P24.9 P24.10 Q3.1(S1) Q3.4(S2) Q4.1(S) Q6.1(S1) Q6.4(S2) Q11.2(SOURCE) Q12.2(SOURCE) Q13.2(SOURCE) Q14.2(SOURCE) Q15.2(SOURCE) R2.1 R42.2 R45.2 R51.1 R89.1 R92.1 R149.1 R155.1 R184.2 R187.2 R190.2 R196.2 R197.2 R199.2 R204.2 R206.2 R212.2 R213.2 R214.2 R222.2 R237.2 R239.2 R241.2 R243.2 R245.2 R249.2 R325.1 RN17.2(RB1) RN17.3(RC1) RN17.4(RD1) SW1.1 U29.4(GND) U29.9(PAD) U30.4(GND) U30.9(PAD) U31.4(GND) U32.4(GND) U32.9(PAD) U35.9(VSS) U35.25(CPAD) U37.B1(SPKGND1) U37.C1(SPKGND2) U37.C7(CPGND) U37.D7(AGND) U37.F2(CIFMODE) U37.F3(DGND) U37.G5(PLLGND) U40.4(GND) U40.9(PAD) U43.3(GND) U48.B3(VSS1) U48.C1(VSS2) U48.E5(VSS3) U59.2(GND) U63.Tpad X3.2 X3.4 ; also on sheet 2 3 4 5 6 7
V1V8_BOOT: C197.1 U40.2(BOOT)
V1V8_COMP: C184.1 C206.1 U40.6(COMP)
V1V8_COMP_C: C206.2 R206.1
V1V8_EN: R219.2 R221.1 U40.3(EN)
V1V8_FB: R222.1 R223.2 U40.5(FB)
V1V8_RLIM: R204.1 U40.7(RLIM)
V1V8_SW: C197.2 L32.1 U40.1(SW)
V3V3_BOOT: C174.1 U30.2(BOOT)
V3V3_COMP: C180.1 C183.1 U30.6(COMP)
V3V3_COMP_C: C180.2 R199.1
V3V3_EN: R200.2 R202.1 U30.3(EN)
V3V3_FB: R197.1 R198.2 U30.5(FB)
V3V3_RLIM: R196.1 U30.7(RLIM)
V3V3_SW: C174.2 L21.1 U30.1(SW)
V5_BOOT: C189.1 U32.2(BOOT)
V5_COMP: C191.1 C196.1 U32.6(COMP)
V5_COMP_C: C191.2 R214.1
V5_FB: R208.2 R212.1 U32.5(FB)
V5_RLIM: R213.1 U32.7(RLIM)
V5_SW: C189.2 L22.1 U32.1(SW)
V5V0_EN: R203.2 R205.1 U32.3(EN)
VCC_1V8: C77.1 C86.1 C103.1 C104.1 C181.2 C192.2 C203.2 D14.ANODE J4.14 J4.50 L23.2 L32.2 P11.2 R64.1 R67.1 R68.1 R71.1 R75.1 R156.1 R157.1 R223.1 R362.1 R363.1 U48.B4(VCC1) U48.D1(VCC2) U48.E4(VCC3)
VCC_1V8_D: Q13.3(DRAIN) R156.2 R157.2
VCC_3V3: C59.1 C62.1 C63.1 C68.1 C75.1 C76.1 C79.1 C84.1 C98.2 C99.2 C100.2 C101.2 C158.2 C175.2 C179.2 C193.1 C211.1 C251.2 C258.1 C259.2 C373.1 DS4.ANODE DS5.ANODE J4.19 J4.49 L21.2 L29.2 P10.1 P15.1 P16.1 P18.1 P19.1 P20.1 Q4.5(G) R1.2 R61.2 R151.1 R154.1 R159.2 R166.2 R167.2 R198.1 R235.1 R240.1 R244.1 R261.1 U31.8(VCC) U35.21(VDD) U37.A3(MICVDD) U37.G3(DBVDD) U59.5(VIO) U63.1(VDD) U63.6(VDD_1) U63.13(VDD_2) U63.26(VDD_3) ; also on sheet 2 3 4 5 6 7
VCC_3V3_D: Q12.3(DRAIN) R151.2 R154.2
VCC_5V0: C188.2 C190.2 C371.2 L22.2 L24.2 P17.1 R161.1 R165.1 R208.1 U59.3(VCC) ; also on sheet 5 7
VCC_5V0_D: Q14.3(DRAIN) R161.2 R165.2
VCC_RTC: R231.2 ; also on sheet 2
ADC_IN0: P24.2 ; also on sheet 2
ADC_IN1: P24.4 ; also on sheet 2
ADC_IN2: P24.6 ; also on sheet 2
ADC_IN3: P24.8 ; also on sheet 2
ADC_IN4: P24.1 ; also on sheet 2
ADC_IN5: P24.3 ; also on sheet 2
ADC_IN6: P24.5 ; also on sheet 2
ADC_IN7: P24.7 ; also on sheet 2
AJ_CO: J6.CO R240.2
AUD_SCL: R250.1 U37.F1(SCLK)
AUD_SDA: R247.1 U37.E2(SDA)
C_VOTN: C262.1 U37.A7(CPVOUTN)
C_VOTP: C239.1 U37.A6(CPVOUTP)
CAN2_RX: U59.4(RXD) ; also on sheet 2
CAN2_TX: U59.1(TXD) ; also on sheet 2
CAN_H: P17.2 R6.2 U59.7(CANH)
CAN_L: E6.1 P17.6 U59.6(CANL)
CAN_STBY: R325.2 U59.8(STBY)
CAN_T: E6.2 R6.1
CLKOUT2: TP2.1 U37.E4(CLKOUT2/GPIO2)
CLKOUT5: TP4.1 U37.G6(CLKOUT5)
CODEC_INT: R244.2 R248.2 U37.E3(~{CS}/GPIO6)
COLD_RESET_IN: D10.ANODE P10.3 ; also on sheet 2
CPCA: C254.1 U37.B6(CPCA)
CPCB: C254.2 U37.B7(CPCB)
CSI1_CTRL: J4.20 U35.10(I/O1.0)
CSI1_FLASH_OUT: J4.24 U35.12(I/O1.2)
CSI1_PWR_DWN: J4.21 U35.7(I/O0.6)
CSI1_RST: J4.23 U35.8(I/O0.7)
CSI1_TRG: J4.22 U35.11(I/O1.1)
CSI2_CTRL: J4.44 U35.15(I/O1.5)
CSI2_FLASH_OUT: J4.48 U35.17(I/O1.7)
CSI2_PWR_DWN: J4.45 U35.13(I/O1.3)
CSI2_RST: J4.47 U35.14(I/O1.4)
CSI2_TRG: J4.46 U35.16(I/O1.6)
CSI_DSI_SELECT: R61.1 R62.2 U63.16(SEL1) U63.17(SEL2)
CSIDSI_SELECT_J: E7.1 R62.1
DC_FLT: C277.1 FB1.2 FB2.2 Q1.1(S) Q1.2(S) Q1.3(S) R259.2 R289.2
DC_JACK: C22.1 D9.CATHODE FB1.1 FB2.1 J1.1(CENTRAL)
DC_LED: DS2.ANODE R289.1
DISCH_ON_H: Q11.1(GATE) Q12.1(GATE) Q13.1(GATE) Q14.1(GATE) Q15.1(GATE) R42.1 R266.2
DISCH_ONH: R266.1 R268.2 SW1.2
DS3_G#: Q6.3(D2) R91.1
DS3_R#: Q6.6(D1) R90.1
DSI_DISP_RESET: U35.3(I/O0.2) ; also on sheet 7
EEPROM_WP: R149.2 U31.7(WP)
EPR_A2: R1.1 R2.2 U31.3(A2)
EXPANDER_A0: R166.1 RN17.5(RD2) U35.18(A0)
EXPANDER_A1: R167.1 RN17.6(RC2) U35.23(A1)
EXPANDER_A2: R159.1 RN17.7(RB2) U35.24(A2)
GPIO1_IO11: P18.6 ; also on sheet 2
GPIO1_IO14: P18.2 ; also on sheet 2
GPIO4_IO28_1V8: Q6.2(G1) R89.2 ; also on sheet 2
GPIO4_IO29_1V8: Q6.5(G2) R92.2 ; also on sheet 2
GPIO_IO08: P18.4 ; also on sheet 2
GPIO_IO22: R248.1 ; also on sheet 2
GPIO_IO32: P18.3 ; also on sheet 2
HP_FB: R249.1 U37.B4(HPOUTFB)
HP_J_D: J6.CN R236.1 R237.1
HP_JD: R236.2 R261.2 U37.G1(GPIO5)
HP_MICH: TP3.1 U37.F4(CLKOUT3/GPIO3)
HPOUT_L: C232.1 L31.2 R245.1 U37.B5(HPOUTL)
HPOUT_L_C: C232.2 R239.1
HPOUT_L_F: C235.2 J6.4(L) L31.1
HPOUT_R: C255.1 L26.2 R243.1 U37.A5(HPOUTR)
HPOUT_R_C: C255.2 R241.1
HPOUT_R_F: C264.2 J6.3(R) L26.1
I2C3_SCL: R250.2 U31.6(SCL) U35.19(SCL) ; also on sheet 2 6 7
I2C3_SDA: R247.2 U31.5(SDA) U35.20(SDA) ; also on sheet 2 6 7
I2C4_SCL: R368.2 ; also on sheet 2
I2C4_SDA: R369.2 ; also on sheet 2
I2C8_SCL: P16.5 R364.2 R366.2 ; also on sheet 2
I2C8_SDA: P16.3 R365.2 R367.2 ; also on sheet 2
INT_EXP: R235.2 U35.22(\\~{IN}T)
J_MOD_8: P11.8 R155.2
JTAG_HDR_10: P11.10 R51.2
JTAG_RST: D10.CATHODE P11.9 R330.2
JTAG_RST_PU: D14.CATHODE R330.1
JTAG_TCK: P11.3 ; also on sheet 2
JTAG_TDI: P11.7 R363.2 ; also on sheet 2
JTAG_TDO: P11.5 ; also on sheet 2
JTAG_TMS: P11.1 R362.2 ; also on sheet 2
LED_G: DS4.CATHODE R90.2
LED_Y: DS5.CATHODE R91.2
LLINEIN: C252.2 C261.1 U37.E6(IN4L)
LLINEIN_C: C261.2 J5.4(L)
LVDS0_DISP_RESET: U35.4(I/O0.3) ; also on sheet 7
LVDS1_DISP_RESET: U35.6(I/O0.5) ; also on sheet 7
MICBIAS: C241.1 U37.A4(MICBIAS)
MIPI_CSI1_CLK_N: J4.6 ; also on sheet 2
MIPI_CSI1_CLK_P: J4.4 ; also on sheet 2
MIPI_CSI1_D0_N: J4.5 ; also on sheet 2
MIPI_CSI1_D0_P: J4.3 ; also on sheet 2
MIPI_CSI1_D1_N: J4.12 ; also on sheet 2
MIPI_CSI1_D1_P: J4.10 ; also on sheet 2
MIPI_CSI1_D2_N: J4.11 ; also on sheet 2
MIPI_CSI1_D2_P: J4.9 ; also on sheet 2
MIPI_CSI1_D3_N: J4.17 ; also on sheet 2
MIPI_CSI1_D3_P: J4.15 ; also on sheet 2
MIPI_CSI1_I2C_SCL: J4.16 R364.1
MIPI_CSI1_I2C_SDA: J4.18 R365.1
MIPI_CSI2_CLK_N: J4.30 U63.31(NO1-)
MIPI_CSI2_CLK_P: J4.28 U63.32(NO1+)
MIPI_CSI2_D0_N: J4.29 U63.29(NO2-)
MIPI_CSI2_D0_P: J4.27 U63.30(NO2+)
MIPI_CSI2_D1_N: J4.36 U63.27(NO3-)
MIPI_CSI2_D1_P: J4.34 U63.28(NO3+)
MIPI_CSI2_D2_N: J4.35 U63.20(NO4-)
MIPI_CSI2_D2_P: J4.33 U63.21(NO4+)
MIPI_CSI2_D3_N: J4.41 U63.33(NO0-)
MIPI_CSI2_D3_P: J4.39 U63.34(NO0+)
MIPI_CSI2_I2C_SCL: J4.40 R366.1 R368.1
MIPI_CSI2_I2C_SDA: J4.42 R367.1 R369.1
MIPI_DSI_CLK_N: U63.39(NC1-) ; also on sheet 7
MIPI_DSI_CLK_P: U63.40(NC1+) ; also on sheet 7
MIPI_DSI_D0_N: U63.37(NC2-) ; also on sheet 7
MIPI_DSI_D0_P: U63.38(NC2+) ; also on sheet 7
MIPI_DSI_D1_N: U63.35(NC3-) ; also on sheet 7
MIPI_DSI_D1_P: U63.36(NC3+) ; also on sheet 7
MIPI_DSI_D2_N: U63.24(NC4-) ; also on sheet 7
MIPI_DSI_D2_P: U63.25(NC4+) ; also on sheet 7
MIPI_DSI_D3_N: U63.41(NC0-) ; also on sheet 7
MIPI_DSI_D3_P: U63.42(NC0+) ; also on sheet 7
MIPI_DSICSI_CLK_N: U63.5(COM1-) ; also on sheet 2
MIPI_DSICSI_CLK_P: U63.4(COM1+) ; also on sheet 2
MIPI_DSICSI_D0_N: U63.8(COM2-) ; also on sheet 2
MIPI_DSICSI_D0_P: U63.7(COM2+) ; also on sheet 2
MIPI_DSICSI_D1_N: U63.10(COM3-) ; also on sheet 2
MIPI_DSICSI_D1_P: U63.9(COM3+) ; also on sheet 2
MIPI_DSICSI_D2_N: U63.12(COM4-) ; also on sheet 2
MIPI_DSICSI_D2_P: U63.11(COM4+) ; also on sheet 2
MIPI_DSICSI_D3_N: U63.3(COM0-) ; also on sheet 2
MIPI_DSICSI_D3_P: U63.2(COM0+) ; also on sheet 2
MODEM_RF_KILL#: U35.1(I/O0.0) ; also on sheet 6
OCTAL_SPI_RESET_B: C105.1 R73.2 R74.2 U48.A4(~{RESET})
OCTAL_SPI_VPP: C102.1 R67.2 U48.C5(VPP)
PMIC_ON_REQ: P10.6 Q3.5(G2) ; also on sheet 2
PMIC_ON_REQn: Q3.2(G1) Q3.3(D2) R230.2
PMIC_STBY_REQ: P10.4 Q4.2(G) ; also on sheet 2
POR_B_1V8: Q4.3(D) R74.1 R75.2
POR_B_3V3: Q4.4(S) ; also on sheet 2
PWR_CTRL: R200.1 R203.1 R219.1 R228.2 U43.4(Y)
PWR_CTRL_IN: Q3.6(D1) Q4.6(D) R224.2 R228.1 U43.2(A)
RLINEIN: C234.2 C257.1 U37.E7(IN4R)
RLINEIN_C: C257.2 J5.3(R)
SAI3_MCLK: R254.2 ; also on sheet 2
SAI3_RXD: U37.D2(ADCDAT) ; also on sheet 2
SAI3_TXC: U37.E1(BCLK) ; also on sheet 2
SAI3_TXD: U37.D1(DACDAT) ; also on sheet 2
SAI3_TXFS: U37.D3(LRCLK) ; also on sheet 2
SPDIF_AUDIO_OUT: C54.1 P10.2 R45.1 R48.2
SPDIF_TX: C53.2 ; also on sheet 2
SPDIF_TX_C: C53.1 R48.1
SPI7_CS0: P15.4 ; also on sheet 2
SPI7_MISO: P15.2 ; also on sheet 2
SPI7_MOSI: P15.3 ; also on sheet 2
SPI7_SCLK: P15.5 ; also on sheet 2
TOUCH_RESET: U35.5(I/O0.4) ; also on sheet 7
UART2_CTS#: P19.6 ; also on sheet 2
UART2_RTS#: P19.3 ; also on sheet 2
UART2_RXD: P19.2 ; also on sheet 2
UART2_TXD/BT_MODE1: P19.4 ; also on sheet 2
UART3_RX: P20.2 ; also on sheet 2
UART3_TX: P20.4 ; also on sheet 2
USB_PWR_EN: U35.2(I/O0.1) ; also on sheet 5
V_COIN: BH1.1P(+) BH1.3P(+) R231.1
V_SOM: C166.2 C167.2 C207.1 E2.1 R79.1 R150.1 R182.1 R183.2 R202.2 R205.2 R221.2 R224.1 R230.1 U43.5(VCC) ; also on sheet 2 6
V_SOM_D: Q11.3(DRAIN) R79.2 R150.2
V_SOM_L: C164.2 C165.2 E2.2 L20.2 R181.1 R183.1
VDC_IN: C162.1 C163.1 C177.1 C178.1 C186.1 C187.1 C198.1 C199.1 C378.1 C379.1 Q1.5(D) Q1.6(D) Q1.7(D) Q1.8(D) Q1.9(D-pad) R174.1 R175.1 R180.2 U29.8(VIN) U30.8(VIN) U32.8(VIN) U40.8(VIN)
VDC_IN_D: Q15.3(DRAIN) R174.2 R175.2
VGS_Q5: C277.2 Q1.4(G) R259.1 R268.1
VMIDC: C266.2 U37.C5(VMIDC)
VSOM_BOOT: C161.1 U29.2(BOOT)
VSOM_COMP: C172.1 C173.1 U29.6(COMP)
VSOM_COMP_C: C172.2 R190.1
VSOM_EN: R180.1 U29.3(EN)
VSOM_FB: R181.2 R187.1 U29.5(FB)
VSOM_LED: DS3.ANODE R182.2
VSOM_RLIM: R184.1 U29.7(RLIM)
VSOM_SW: C161.2 L20.1 U29.1(SW)
XSPI_CLK: R72.1 ; also on sheet 2
XSPI_CLK_R: R72.2 U48.B2(C)
XSPI_DATA0: R64.2 U48.D3(DQ0) ; also on sheet 2
XSPI_DATA1: U48.D2(DQ1) ; also on sheet 2
XSPI_DATA2: R68.2 U48.C4(DQ2/~{W}) ; also on sheet 2
XSPI_DATA3: U48.D4(DQ3) ; also on sheet 2
XSPI_DATA4: U48.D5(DQ4) ; also on sheet 2
XSPI_DATA5: U48.E3(DQ5) ; also on sheet 2
XSPI_DATA6: U48.E2(DQ6) ; also on sheet 2
XSPI_DATA7: U48.E1(DQ7) ; also on sheet 2
XSPI_DQS: R70.2 ; also on sheet 2
XSPI_DQS_R: R70.1 U48.C3(DQS)
XSPI_SS0_B: R71.2 U48.C2(~{S}) ; also on sheet 2
XSPI_SS1_B: R73.1 ; also on sheet 2
XTALI_24M: C246.2 R254.1 R255.1 U37.G7(MCLK/XTI) X3.1
XTALO_24M: C263.2 R255.2 U37.F7(XTO) X3.3

Not connected (* = marked no-connect by the designer): J5 2(AUX)* CN* CO*; J6 2(AUX)*; P10 5* 7*; P15 6* 7*; P16 2* 4* 6* 7*; P17 3* 4* 5* 7*; P18 5* 7* 8* 9*; P19 5* 7*; P20 3* 5* 6* 7*; RN17 1(RA1)* 8(RA2)*; U31 1(NC)* 2(NC)*; U37 A1(SPKOUTLP)* B2(SPKOUTRP)* B3(SPKOUTLN)* C3(SPKOUTRN)* C4(IN1L)* D4(IN1R)* D5(IN2L)* E5(IN2R)* F5(IN3L)* F6(IN3R)*; U48 A2(NC)* A3(RFU2)* A5(RFU1)* B1(RFU3)* B5(RFU4)*; U63 14(COM5+)* 15(COM5-)* 18(NO5-)* 19(NO5+)* 22(NC5-)* 23(NC5+)*

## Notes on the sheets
sheet 8
- Camera Edge Connector
- MIPI-DSICSI Switch
- CSI1
- # 100-Ohm diff pairs
- CSI2
- SILKSCREEN:
  Enable MIPI_CSI2
- OPEN: SEL='1': MIPI_CSI2
  CLOSE: SEL='0' : MIPI_DSI
sheet 9
- Audio Codec
- DCVDD
  DBVDD
  MICVDD
  AVDD
  PLLVDD
  CPVDD
  SPKVDD
- 1.62V - 2.0V
  1.62V - 3.6V
  1.70V - 3.6V
  1.70V - 2.0V
  1.70V - 2.0V
  1.70V - 2.0V
  1.70V - 5.5V
- DNP
- PLUGGED: High
  Removed: Low
- Zobel Networks: close to
  WM8962B
- Plugged: CO
  connected to CN
- DNP
- Clk/Osc enable; p#163; T104/105
- DNP
- DNP
- PLUGGED: High
  Removed: Low
- DNP
- DNP
- XTAL provision
  Not populated
sheet 10
- NOR
- OCTAL SPI FLASH
- User LEDs
- DNP
- SB-UCMIMX95
- DNP
- int PU
- DNP
- NOR
- POR_B
- PU on SOM
sheet 11
- VCC_3V3
- VCC_5V
- Vout=0.8*(1+56.2/17.8)=3.33V
- Vout=5V
  Iout max = 3A
- Vout=3.3V
  Iout max = 3A
- Vout=0.8*(1+64.9/12.4)=4.987V
- RLIM = 100k => ~4A
- RLIM = 100k => ~4A
- DNP
- DNP
- PWR_CTRLn
- V_SOM (4.5A)
- Vout=3.7V
  Iout max = 4.5A
- Current measure
- DNP
- DNP
- Vout=0.8*(1+64.9/17.8)=3.72V
- RLIM = 110k => 4.5A
- VCC_1V8
- VCC_3V3 plane decoupling
- Vout=0.8*(1+22.1/17.8)=1.79V
- Vout=1.8V
  Iout max = 3A
- RLIM = 100k => ~4A
- DNP
sheet 12
- DC input
- Vin 12V
- Discharge
- P-MOSFET, 8.3A, 20V
- -Vgs:2-4.5V
- 3A, 20V
- Vgs:2.7-6.0V
- RTC battery
sheet 13
- CAN bus
- UARTs
- System /Miscellaneous
- EEPROM
- 3.3V x 2mA = 6.6mW
- I2C slave address: 0x54..0x57
- GPIO
- GPIO expander
- SPI
- I2C Address:
  0x20
- I2C
- JTAG
- NXP refdes layout
- TMS
- VCC
- TCK
- GND
- TDI
- TDO
- GND
- ADC
